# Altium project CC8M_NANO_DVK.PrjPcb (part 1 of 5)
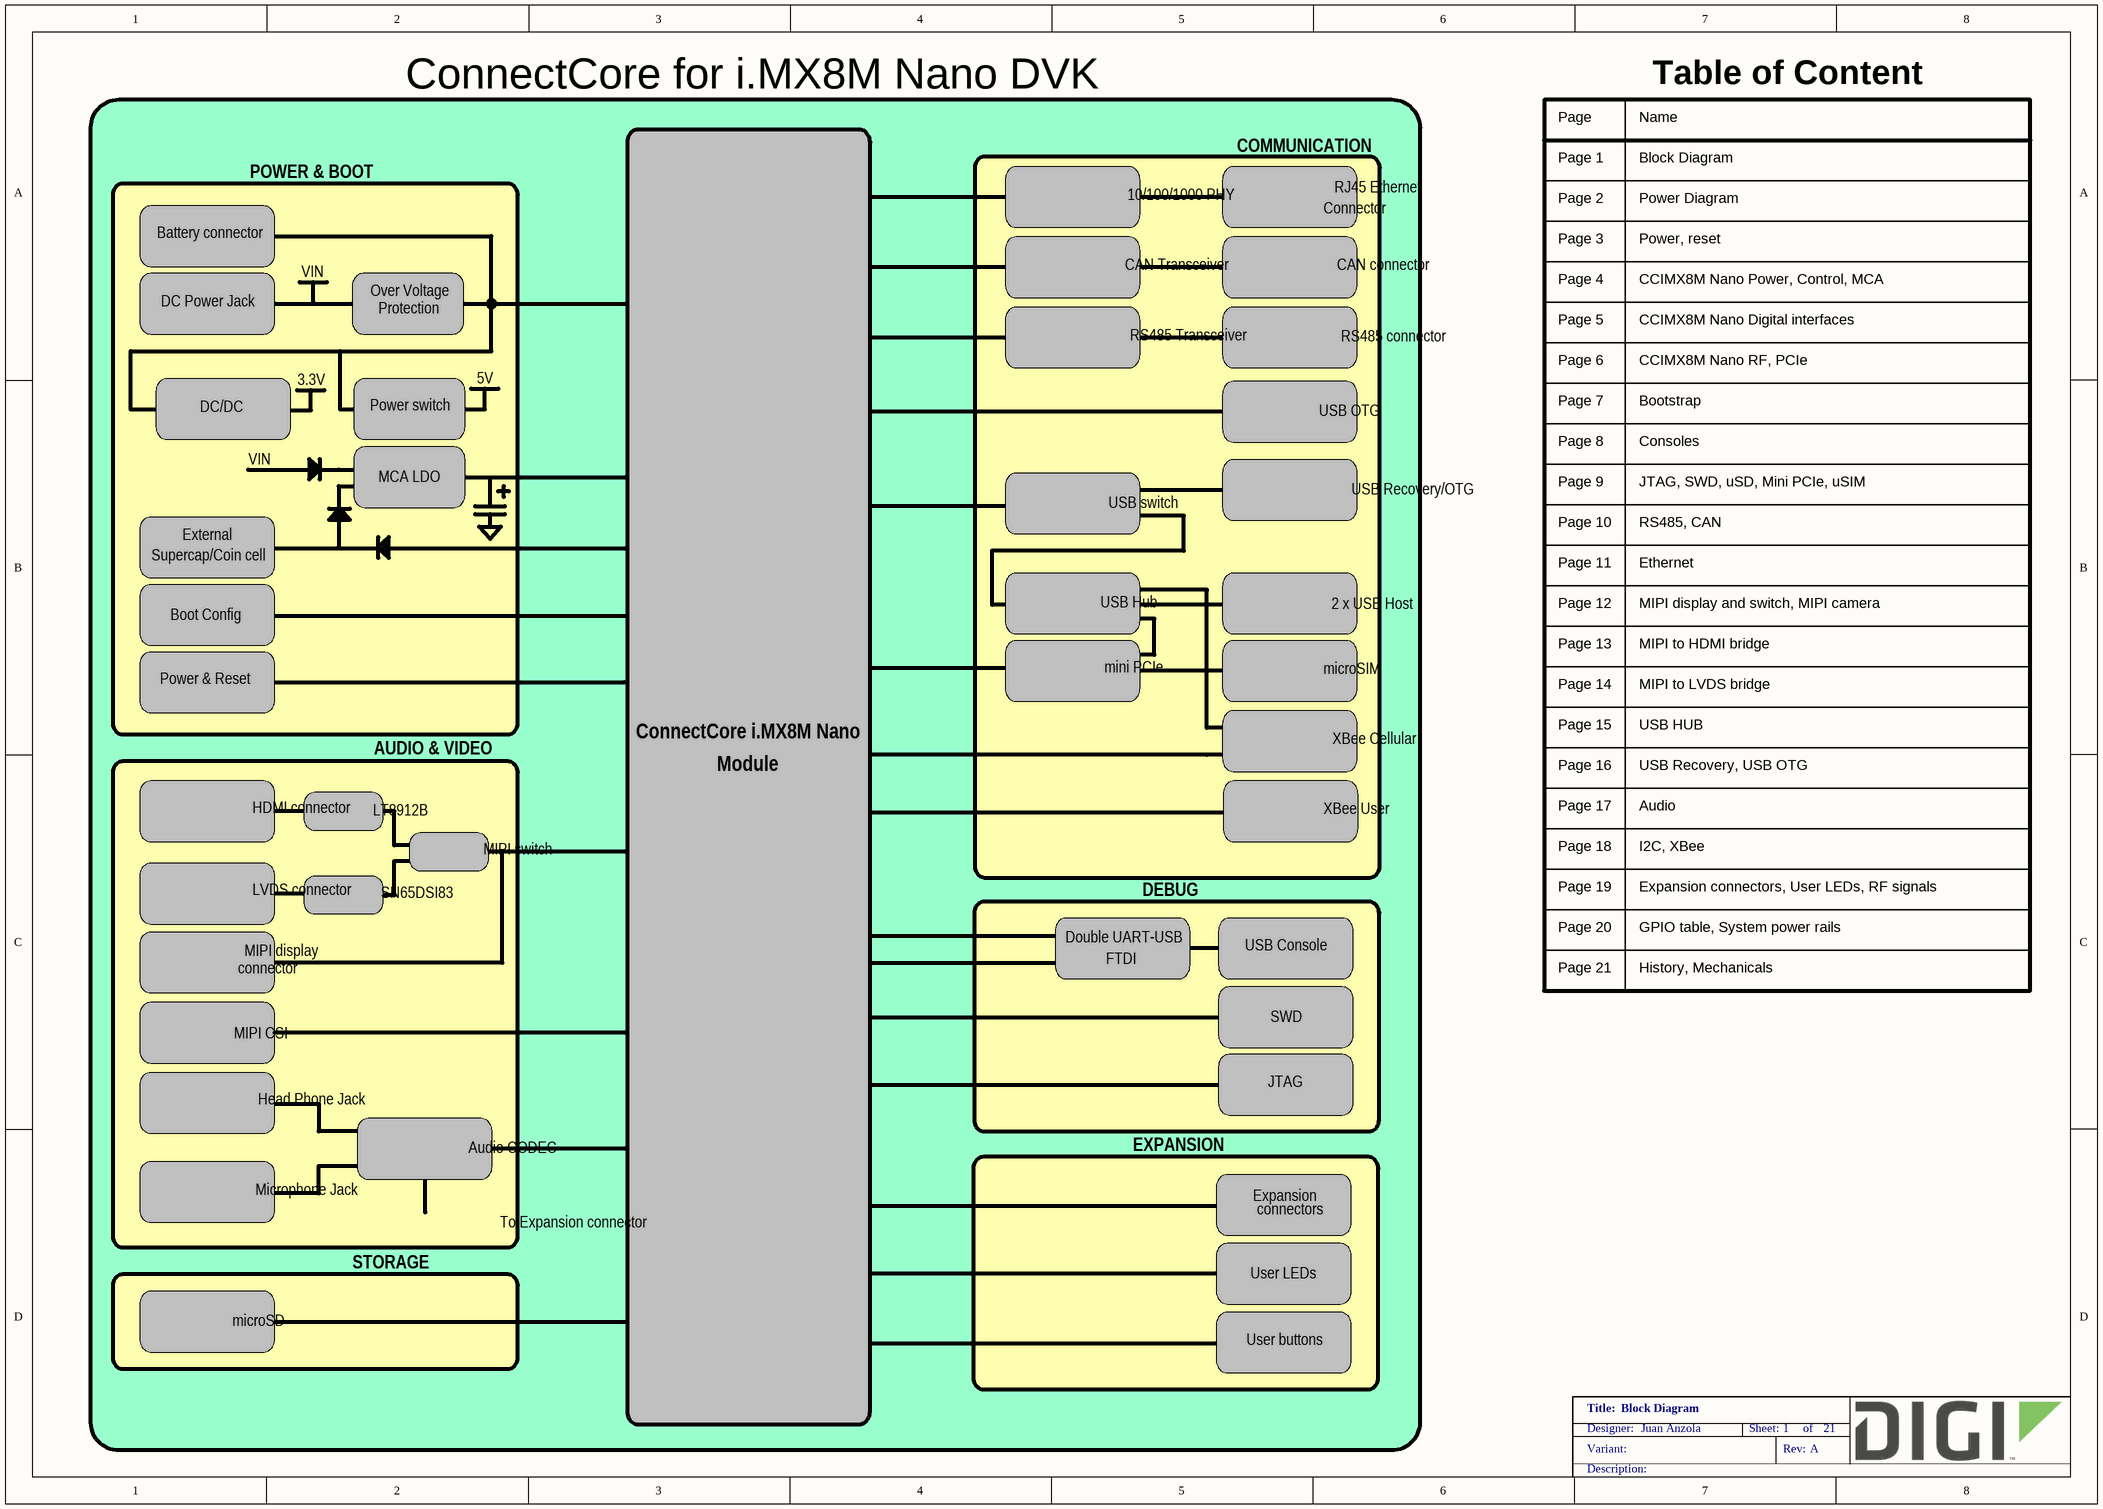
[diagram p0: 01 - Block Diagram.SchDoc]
VariantRevision: A
21 sheets, 756 parts. Net scope: flat (ports and power ports of the same name join across sheets).
Board file: 30016232-02_A.PcbDoc
Sheets:
  01 - Block Diagram.SchDoc
  02 - Power Diagram.SchDoc
  03 - Power, reset.SchDoc
  04 - CCIMX8M Nano Power, Control, MCA.SchDoc
  05 - CCIMX8M Nano Digital interfaces.SchDoc
  06 - CCIMX8M Nano RF, PCIe.SchDoc
  07 - Bootstrap.SchDoc
  08 - Consoles.SchDoc
  09 - JTAG, SWD, uSD, Mini PCIe, uSIM.SchDoc
  10 - RS485, CAN.SchDoc
  11 - Ethernet.SchDoc
  12 - MIPI display and switch, MIPI camera.SchDoc
  13 - MIPI to HDMI bridge.SchDoc
  14 - MIPI to LVDS bridge.SchDoc
  15 - USB HUB.SchDoc
  16 - USB Recovery, USB OTG.SchDoc
  17 - Audio.SchDoc
  18 - I2C, XBee.SchDoc
  19 - Expansion connectors, User LEDs, RF signals.SchDoc
  20 - GPIO Table, I2C Addresses.SchDoc
  21 - History, Mechanicals.SchDoc

## Sheet 01 - Block Diagram.SchDoc: Block Diagram
size A3; PageSetup: Record=PageOptions¦CenterHorizontal=True¦CenterVertical=True¦PrintScale=0.70¦XCorrection=1.00¦YCorrection=1.00¦PrintKind=0¦BorderSize=5000000¦LeftOffset=0¦BottomOffset=0¦Orientation=2¦PaperLength=4200¦PaperWidth=2970¦Scale=100¦PaperSource=7¦PrintQuality=600¦MediaType=1¦DitherType=10¦PaperKind=A4¦PrintScaleMode=1; Author: Juan Anzola; SheetNumber: 1; SheetTotal: 21

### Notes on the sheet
- ConnectCore for i.MX8M Nano DVK
- Table of Content
- POWER & BOOT
- COMMUNICATION
- Page 1
- Page
- Block Diagram
- Name
- Battery connector
- 10/100/1000 PHY
- Connector
- RJ45 Ethernet
- Page 2
- Page 3
- Power, reset
- Power Diagram
- DC Power Jack
- VIN
- Protection
- Over Voltage
- CAN Transceiver
- CAN connector
- Page 4
- CCIMX8M Nano Power, Control, MCA
- 5V
- RS485 Transceiver
- RS485 connector
- Page 5
- Page 6
- CCIMX8M Nano Digital interfaces
- CCIMX8M Nano RF, PCIe
- DC/DC
- 3.3V
- Power switch
- USB OTG
- Page 7
- Page 8
- Consoles
- Bootstrap
- MCA LDO
- USB switch
- USB Recovery/OTG
- Page 9
- JTAG, SWD, uSD, Mini PCIe, uSIM
- Supercap/Coin cell
- External
- Page 10
- Page 11
- RS485, CAN
- Ethernet
- Boot Config
- USB Hub
- 2 x USB Host
- Page 12
- Page 13
- MIPI display and switch, MIPI camera
- MIPI to HDMI bridge
- Power & Reset
- mini PCIe
- microSIM
- Page 14
- MIPI to LVDS bridge
- AUDIO & VIDEO
- ConnectCore i.MX8M Nano
- Module
- XBee Cellular
- Page 15
- Page 16
- USB HUB
- USB Recovery, USB OTG
- HDMI connector
- LT8912B
- MIPI switch
- XBee User
- Page 17
- Page 18
- Audio
- I2C, XBee
- LVDS connector
- SN65DSI83
- DEBUG
- Page 19
- Expansion connectors, User LEDs, RF signals
- connector
- MIPI display
- Double UART-USB
- FTDI
- USB Console
- Page 20
- Page 21
- History, Mechanicals
- GPIO table, System power rails
- MIPI CSI
- SWD
- Head Phone Jack
- JTAG
- Audio CODEC
- EXPANSION
- Microphone Jack
- To Expansion connector
- Expansion
- connectors
- microSD
- STORAGE
- User LEDs
- User buttons

## Sheet 02 - Power Diagram.SchDoc: Power Diagram
size A3; PageSetup: Record=PageOptions¦CenterHorizontal=True¦CenterVertical=True¦PrintScale=0.70¦XCorrection=1.00¦YCorrection=1.00¦PrintKind=0¦BorderSize=5000000¦LeftOffset=0¦BottomOffset=0¦Orientation=2¦PaperLength=4200¦PaperWidth=2970¦Scale=100¦PaperSource=7¦PrintQuality=600¦MediaType=1¦DitherType=10¦PaperKind=A4¦PrintScaleMode=1; Author: Juan Anzola; SheetNumber: 2; SheetTotal: 21
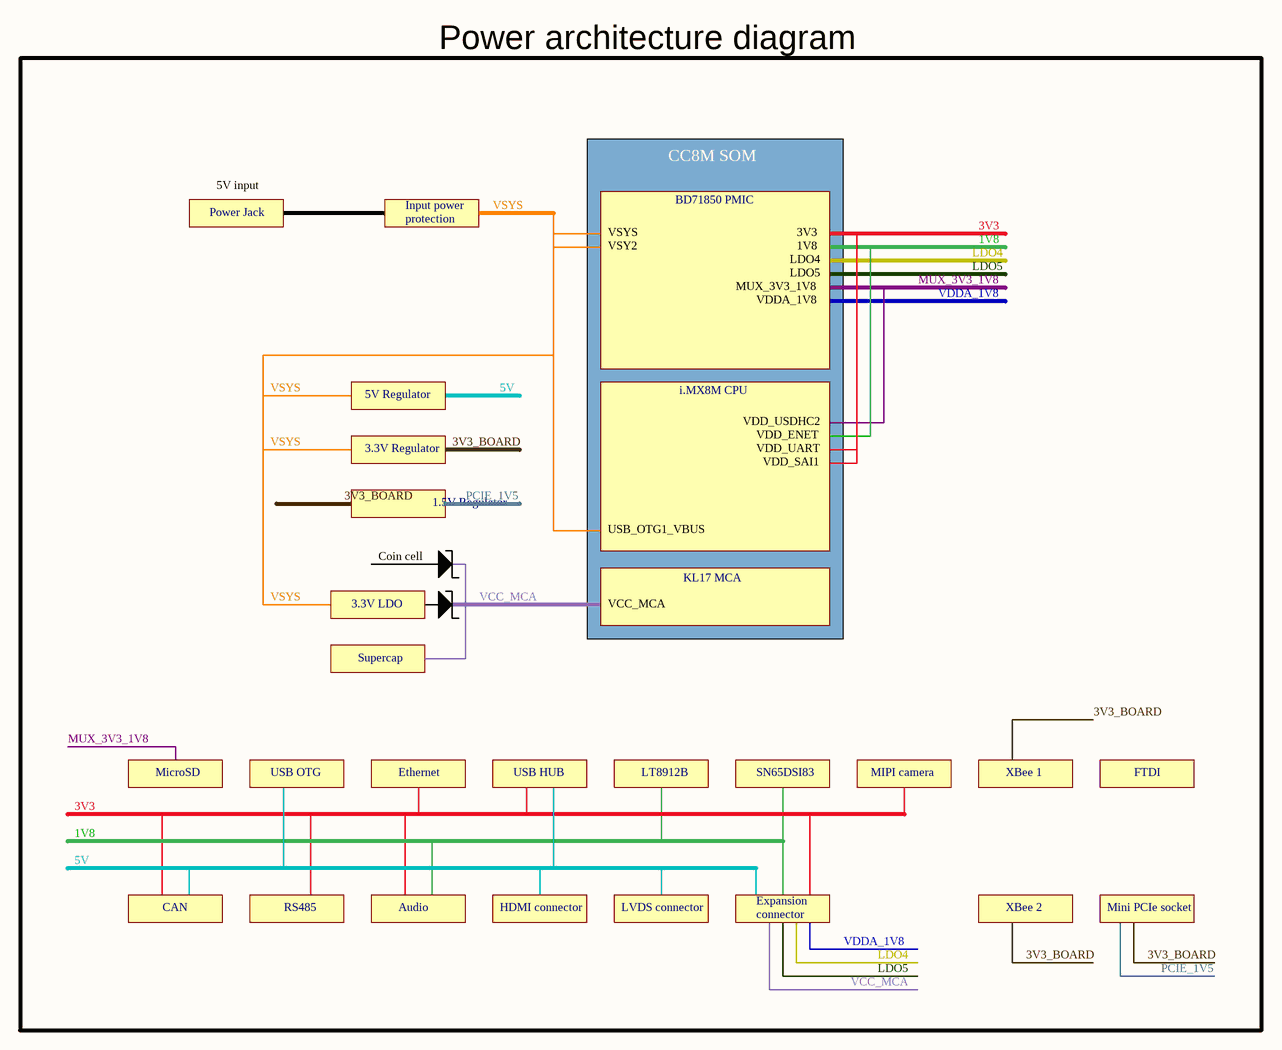
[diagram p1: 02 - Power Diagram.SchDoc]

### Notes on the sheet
- Power architecture diagram
- 5V input
- CC8M SOM
- BD71850 PMIC
- Power Jack
- Input power
- protection
- VSYS
- VSY2
- LDO4
- LDO5
- 3V3
- 1V8
- MUX_3V3_1V8
- VDDA_1V8
- 5V Regulator
- 5V
- i.MX8M CPU
- 3.3V Regulator
- 3V3_BOARD
- VDD_USDHC2
- VDD_ENET
- VDD_UART
- VDD_SAI1
- 1.5V Regulator
- PCIE_1V5
- USB_OTG1_VBUS
- 3.3V LDO
- Coin cell
- VCC_MCA
- KL17 MCA
- Supercap
- MicroSD
- USB OTG
- Ethernet
- USB HUB
- LT8912B
- SN65DSI83
- MIPI camera
- XBee 1
- FTDI
- CAN
- RS485
- Audio
- HDMI connector
- LVDS connector
- Expansion
- connector
- XBee 2
- Mini PCIe socket

## Sheet 03 - Power, reset.SchDoc: Power, reset
size A3; PageSetup: Record=PageOptions¦CenterHorizontal=True¦CenterVertical=True¦PrintScale=0.70¦XCorrection=1.00¦YCorrection=1.00¦PrintKind=0¦BorderSize=5000000¦LeftOffset=0¦BottomOffset=0¦Orientation=2¦PaperLength=4200¦PaperWidth=2970¦Scale=100¦PaperSource=7¦PrintQuality=600¦MediaType=1¦DitherType=10¦PaperKind=A4¦PrintScaleMode=1; Author: Juan Anzola; SheetNumber: 3; SheetTotal: 21
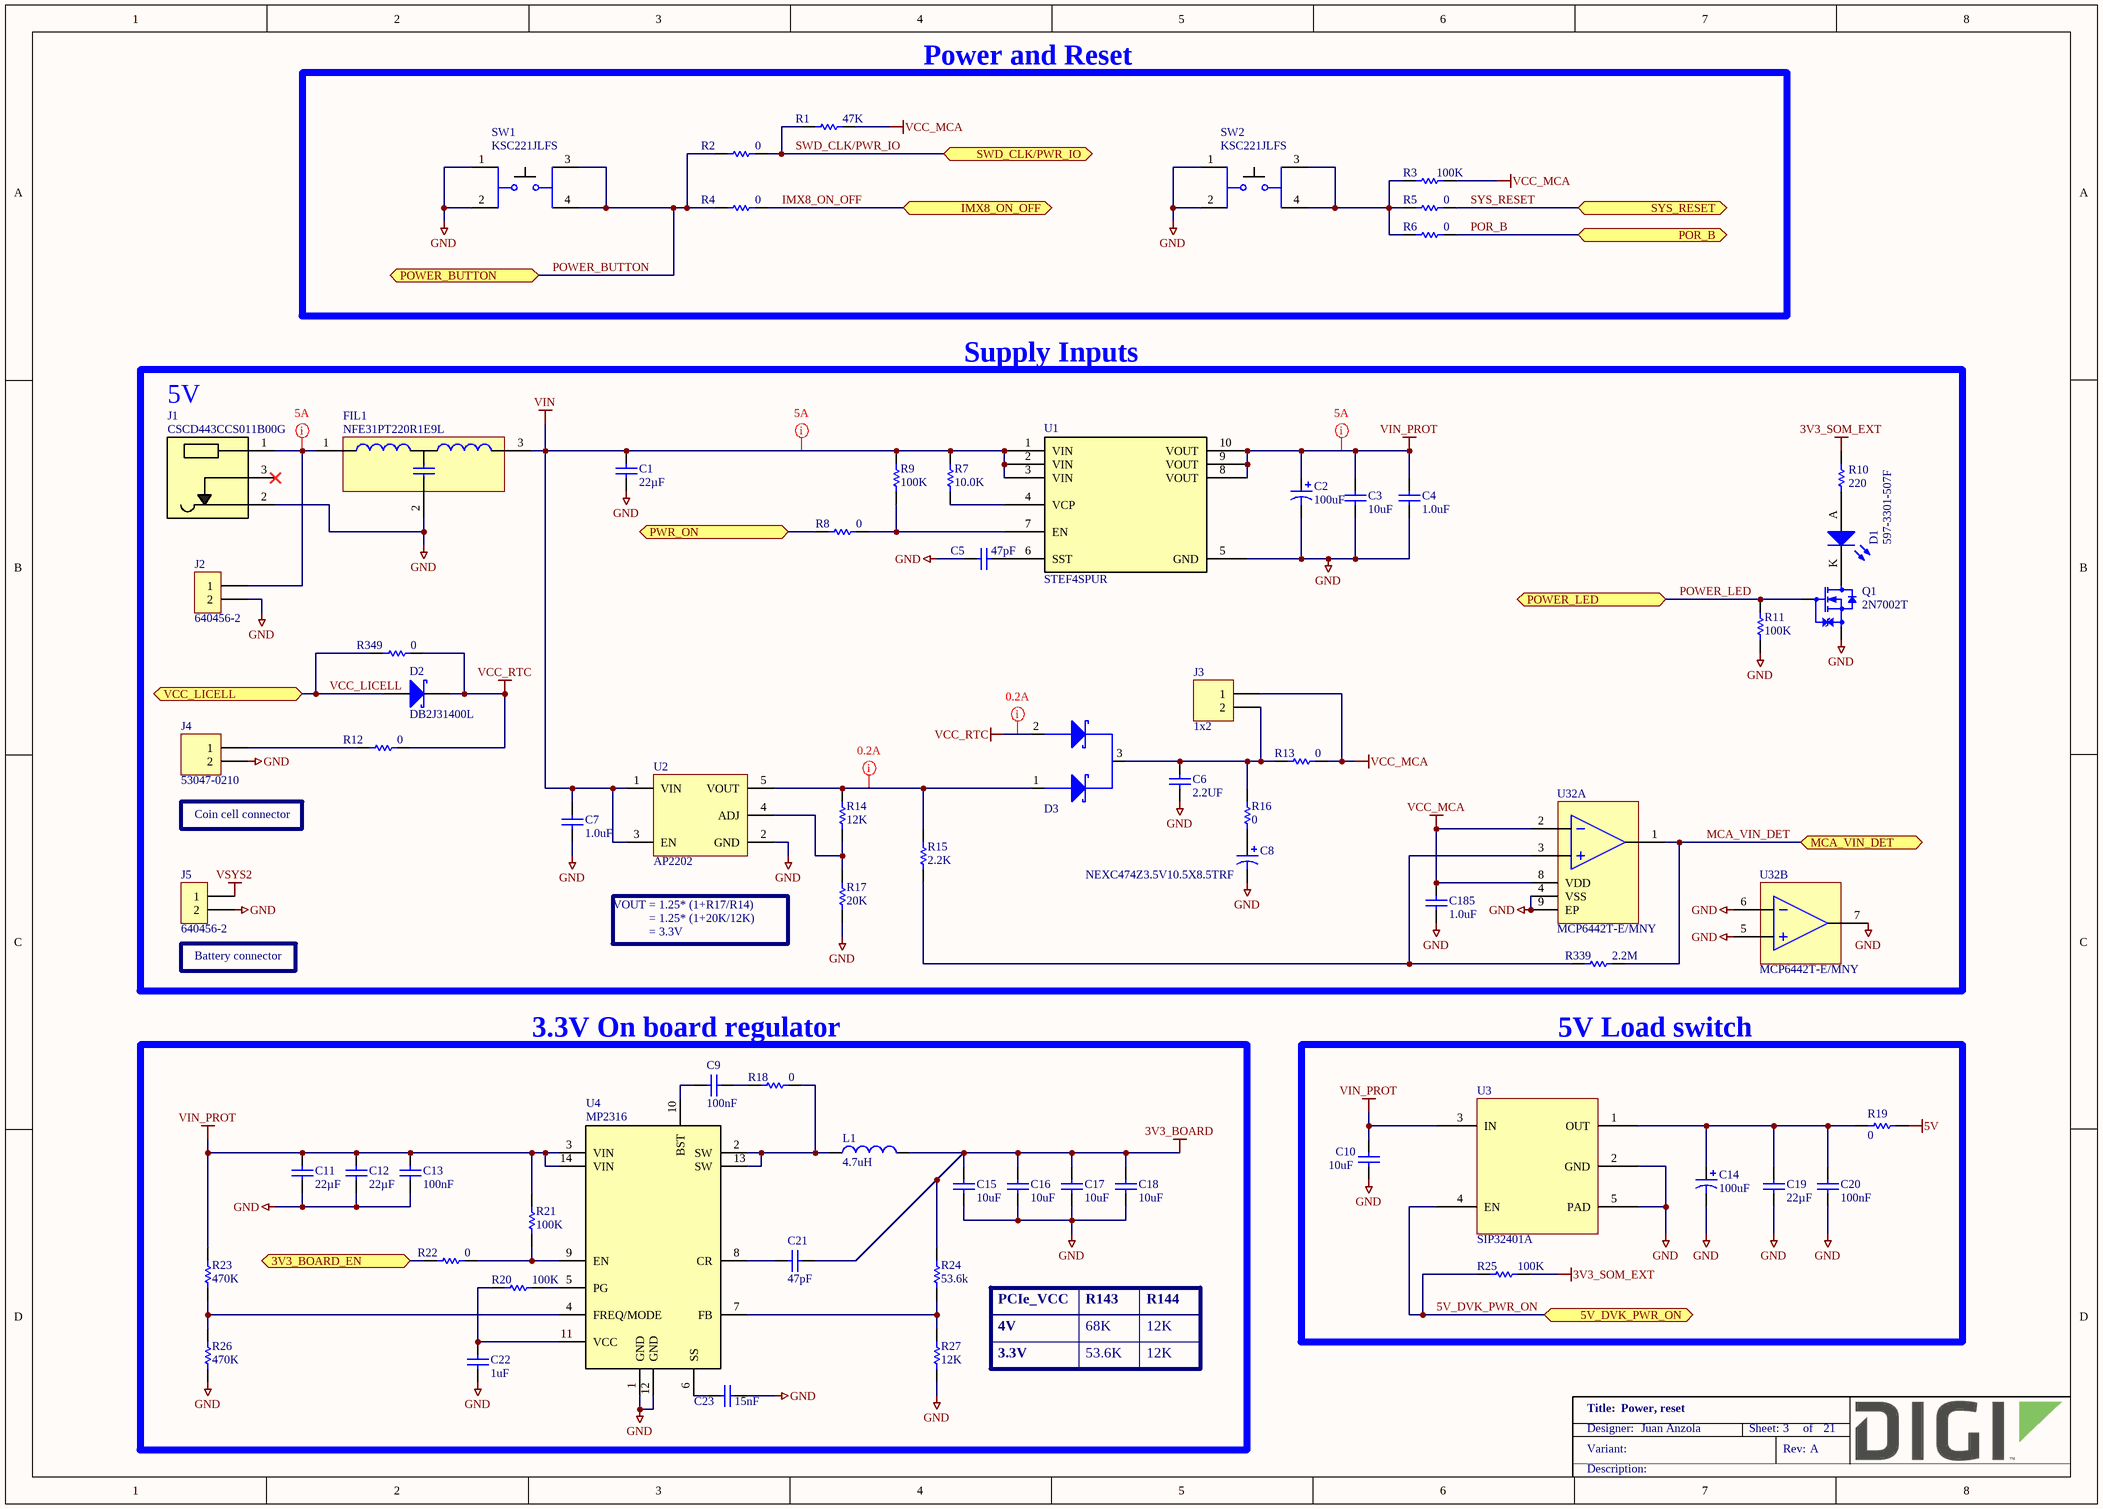
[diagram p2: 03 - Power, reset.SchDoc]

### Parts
C1  22µF  [CAPC1608X90N]
C2  100uF  [CAPMP3216X120N]
C3  10uF  [CAPC1005X55N]
C4  1.0uF  [CAPC1005X55N]
C5  47pF  [CAPC1005X55N]
C6  2.2UF  [CAPC1608X90N]
C7  1.0uF  [CAPC1005X55N]
C8  NEXC474Z3.5V10.5X8.5TRF  [NEXC474Z3.5V10.5X8.5TRF]
C9  100nF  [CAPC1005X55N]
C10  10uF  [CAPC1005X55N]
C11  22µF  [CAPC1608X90N]
C12  22µF  [CAPC1608X90N]
C13  100nF  [CAPC1005X55N]
C14  100uF  [CAPMP3216X120N]
C15  10uF  [CAPC2013X135N]
C16  10uF  [CAPC2013X135N]
C17  10uF  [CAPC2013X135N]
C18  10uF  [CAPC2013X135N]
C19  22µF  [CAPC1608X90N]
C20  100nF  [CAPC1005X55N]
C21  47pF  [CAPC1005X55N]
C22  1uF  [CAPC1608X90N]
C23  15nF  [CAPC1005X55N]
C185  1.0uF  [CAPC1005X55N]
D1  597-3301-507F  [LEDM3020X130N]
D2  DB2J31400L  [SODFL2513X80N]
D3  BAT54CWT1G  [SOT65P210X100-3AN]  (value not drawn)
FIL1  NFE31PT220R1E9L  [FIL_NFE31P]
J1  CSCD443CCS011B00G  [conn_CSCD443CCS011B00G]
J2  640456-2  [TE_640456-2]
J3  1x2  [FCI_68002-102HLF]
J4  Manufacturer_Part_Number: 53047-0210  [MOLEX_53047-0210_Flex]  (hidden comment: 1x2P)
J5  640456-2  [TE_640456-2]
L1  4.7uH  [IND_DG6045C]
Q1  2N7002T  [SOTFL50P160X80_GSD-3N]
R1  47K  [RESC1005X40N]
R2  0  [RESC1005X40N]
R3  100K  [RESC1005X40N]
R4  0  [RESC1005X40N]
R5  0  [RESC1005X40N]
R6  0  [RESC1005X40N]
R7  10.0K  [RESC1005X40N]
R8  0  [RESC1005X40N]
R9  100K  [RESC1005X40N]
R10  220  [RESC1005X40N]
R11  100K  [RESC1005X40N]
R12  0  [RESC1609X55N]
R13  0  [RESC1609X55N]
R14  12K  [RESC1609X55N]
R15  2.2K  [RESC1005X40N]
R16  0  [RESC1005X40N]
R17  20K  [RESC1609X55N]
R18  0  [RESC1609X55N]
R19  0  [RESC1609X55N]
R20  100K  [RESC1005X40N]
R21  100K  [RESC1005X40N]
R22  0  [RESC1005X40N]
R23  470K  [RESC1005X40N]
R24  53.6k  [RESC1609X55N]
R25  100K  [RESC1005X40N]
R26  470K  [RESC1005X40N]
R27  12K  [RESC1609X55N]
R339  2.2M  [RESC0603X28N]
R349  0  [RESC1609X55N]
SW1  KSC221JLFS  [SW_KSC221J]
SW2  KSC221JLFS  [SW_KSC221J]
U1  STEF4SPUR  [SON50P300X300X80-11T164X238N]
U2  AP2202  [SOT95P280X145-5N]
U3  SIP32401A  [SON50P120X160X60-5T55X91N]
U4  MP2316  [QFN_MPS_MP2316]
U32  MCP6442T-E/MNY  [SON50P300X200X80-9N]  (parts A,B of 2)

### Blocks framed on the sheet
Power and Reset: R1-R6 SW1 SW2
Supply Inputs: C1-C8 C185 D1-D3 FIL1 J1-J5 Q1 R7-R17 R339 R349 U1 U2 U32
3.3V On board regulator: C9 C11-C13 C15-C18 C21-C23 L1 R18 R20-R24 R26 R27 U4
5V Load switch: C10 C14 C19 C20 R19 R25 U3

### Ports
3V3_BOARD_EN (bidir), 5V_DVK_PWR_ON (bidir), IMX8_ON_OFF (bidir), MCA_VIN_DET (bidir), POR_B (bidir), POWER_BUTTON (bidir), POWER_LED (bidir), PWR_ON (bidir), SWD_CLK/PWR_IO (bidir), SYS_RESET (bidir), VCC_LICELL (bidir)

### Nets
3V3_BOARD: C15.2 C16.2 C17.2 C18.2 C21.2 L1.2 R24.2
3V3_SOM_EXT: R10.2 R25.2
5V: R19.2
GND: C1.1 C2.2 C3.1 C4.1 C5.1 C6.1 C7.1 C8.2 C10.1 C11.1 C12.1 C13.1 C14.2 C15.1 C16.1 C17.1 C18.1 C19.1 C20.1 C22.1 C23.1 C185.1 FIL1.2 J1.2 J2.2 J4.2 J5.2 Q1.S R11.2 R17.1 R26.1 R27.1 SW1.1 SW1.2 SW2.1 SW2.2 U1.5(GND) U2.2(GND) U3.2(GND) U3.5(PAD) U4.1(GND) U4.12(GND) U32.4(VSS) U32.5(VINB+) U32.6(VINB-) U32.7(VOUTB) U32.9(EP)
VCC_MCA: C185.2 J3.1 R1.2 R3.2 R13.2 U32.2(VIN-) U32.8(VDD)
VCC_RTC: D2.K D3.2 R12.2 R349.2
VIN: C1.2 C7.2 FIL1.3(GND) R7.2 R9.2 U1.1(VIN) U1.2(VIN) U1.3(VIN) U2.1(VIN) U2.3(EN)
VIN_PROT: C2.1 C3.2 C4.2 C10.2 C11.2 C12.2 C13.2 R21.2 R23.2 U1.8(VOUT) U1.9(VOUT) U1.10(VOUT) U3.3(IN) U4.3(VIN) U4.14(VIN)
VSYS2: J5.1
3V3_BOARD_EN: R22.1 ; port 3V3_BOARD_EN
5V_DVK_PWR_ON: R25.1 U3.4(EN) ; port 5V_DVK_PWR_ON
IMX8_ON_OFF: R4.2 ; port IMX8_ON_OFF
MCA_VIN_DET: R339.2 U32.1(VOUT) ; port MCA_VIN_DET
POR_B: R6.2 ; port POR_B
POWER_BUTTON: R2.1 R4.1 SW1.3 SW1.4 ; port POWER_BUTTON
POWER_LED: Q1.G R11.1 ; port POWER_LED
PWR_ON: R8.1 ; port PWR_ON
SWD_CLK/PWR_IO: R1.1 R2.2 ; port SWD_CLK/PWR_IO
SYS_RESET: R5.2 ; port SYS_RESET
VCC_LICELL: D2.A R349.1 ; port VCC_LICELL
NetC5_2: C5.2 U1.6(SST)
NetC6_2: C6.2 D3.3 J3.2 R13.1 R16.2
NetC8_1: C8.1 R16.1
NetC9_1: C9.1 U4.10(BST)
NetC9_2: C9.2 R18.1
NetC14_1: C14.1 C19.2 C20.2 R19.1 U3.1(OUT)
NetC21_1: C21.1 U4.8(CR)
NetC22_2: C22.2 R20.1 U4.11(VCC)
NetC23_2: C23.2 U4.6(SS)
NetD1_A: D1.A R10.1
NetD1_K: D1.K Q1.D
NetD3_1: D3.1 R14.2 R15.2 U2.5(VOUT)
NetFIL1_1: FIL1.1(GND) J1.1 J2.1
NetJ4_1: J4.1 R12.1
NetL1_1: L1.1 R18.2 U4.2(SW) U4.13(SW)
NetR3_1: R3.1 R5.1 R6.1 SW2.3 SW2.4
NetR7_1: R7.1 U1.4(VCP)
NetR8_2: R8.2 R9.1 U1.7(EN)
NetR14_1: R14.1 R17.2 U2.4(ADJ)
NetR15_1: R15.1 R339.1 U32.3(VIN+)
NetR20_2: R20.2 U4.5(PG)
NetR21_1: R21.1 R22.2 U4.9(EN)
NetR23_1: R23.1 R26.2 U4.4(FREQ/MODE)
NetR24_1: R24.1 R27.2 U4.7(FB)

Not connected (* = marked no-connect by the designer): J1 3*

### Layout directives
net class 0.2A: NetD3_1, VCC_RTC
net class 5A: NetFIL1_1, VIN, VIN_PROT

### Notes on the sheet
- 5V
- Coin cell connector
- (near J5) Battery connector
- VOUT = 1.25* (1+R17/R14)
  = 1.25* (1+20K/12K)
  = 3.3V
- PCIe_VCC
- R143
- R144
- 4V
- 3.3V
- 68K
- 53.6K
- 12K

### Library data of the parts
C1 = 1000998: CAP CER 22UF 10V 20% X5R 0603; Part_Type: Capacitor; Manufacturer: Samsung; Manufacturer_Part_Number: CL10A226MP8NUNE; Manufacturer_Alt_1: TDK Corporation; Manufacturer_Alt_1_Part_Number: C1608X5R1A226M080AC; Digi_PN: 14050684; Component_Life_Cycle_State: Reviewed; Area: 2,27; Tolerance: 20
C2 C14 = 1001196: CAP TANT 100UF 6.3V 20% 1206; Part_Type: Capacitor; Manufacturer: Rohm; Manufacturer_Part_Number: TCTAL0J107M8R; Digi_PN: 14050490; Component_Life_Cycle_State: Reviewed; Area: 8.01; Project: CCWMX6_SBC board
C3 C10 = 1001168: CAP CER 10UF 10V 20% X5R 0402; Part_Type: Capacitor; Manufacturer: Samsung; Manufacturer_Part_Number: CL05A106MP5NUNC; Digi_PN: 14050689; Component_Life_Cycle_State: Reviewed; Area: 0.95; Project: CCWMX6_SBC board
C4 = 1001167: CAP CER 1UF 10V 10% X5R 0402; Part_Type: Capacitor; Manufacturer: Murata; Manufacturer_Part_Number: GRM155R61A105KE15D; Digi_PN: 14050399; Component_Life_Cycle_State: Reviewed; Area: 0,95; Project: CCWMX6_SBC board
C5 = 1000007: CAP 47pF 50V 5% NP0 0402; Part_Type: Capacitor; Manufacturer: Murata; Manufacturer_Part_Number: GRM1555C1H470JA01D; Manufacturer_Alt_1: AVX Corporation; Manufacturer_Alt_1_Part_Number: 04025A470JAT2A; Note: 14050747 is Digi No. for GE WDNU; Digi_PN: 14050309; Component_Life_Cycle_State: CAD Reviewed; Area: 0,95; Temp_Coef: C0G, NP0
C6 = 1001303: CAP CER 2.2UF 16V 10% X5R 0603; Part_Type: Capacitor; Manufacturer: TDK Corporation; Manufacturer_Part_Number: C1608X5R1C225K080AB; Digi_PN: 14050730; Component_Life_Cycle_State: Reviewed; Area: 2,27; Project: Pinnacle
C7 = 1000073: CAP CER 1UF 6.3V 20% X5R 0402; Part_Type: Capacitor; Manufacturer: Murata; Manufacturer_Part_Number: GRM155R60J105ME19D; Digi_PN: 14050543; Component_Life_Cycle_State: Proven; Area: 0.95; Project: Adjustable Foundation
C8 = 1002775: SMCAP, 0.47F 3.5V SUPERCAP 8.5x10.5x10.8mm SMT; Part_Type: Capacitor; Manufacturer: NIC; Digi_PN: 14050629; Component_Life_Cycle_State: Pending
C9 C13 = 1000006: CAP 100nF 16V 10% X7R 0402; Part_Type: Capacitor; Manufacturer: Murata; Manufacturer_Part_Number: GRM155R71C104KA88D; Digi_PN: 14050552; Component_Life_Cycle_State: CAD Reviewed; Area: 0.95; Project: KITT; Tolerance: 10
C11 C12 C19 = 1000998: CAP CER 22UF 10V 20% X5R 0603; Part_Type: Capacitor; Manufacturer: Samsung; Manufacturer_Part_Number: CL10A226MP8NUNE; Manufacturer_Alt_1: TDK Corporation; Manufacturer_Alt_1_Part_Number: C1608X5R1A226M080AC; Digi_PN: 14050684; Component_Life_Cycle_State: Reviewed; Area: 2.27; Project: ConnectCore i.MX6 module; Tolerance: 20
C15-C18 = 1000111: CAP CER 10UF 16V 10% X5R 0805; Part_Type: Capacitor; Manufacturer: Murata; Manufacturer_Part_Number: GRM21BR61C106KE15L; Digi_PN: 14050701; Component_Life_Cycle_State: Proven; Area: 3.99; Project: Adjustable Foundation; Tolerance: 10
C20 = 1000006: CAP 100nF 16V 10% X7R 0402; Part_Type: Capacitor; Manufacturer: Murata; Manufacturer_Part_Number: GRM155R71C104KA88D; Component_Life_Cycle_State: CAD Reviewed; Area: 0.95; Project: KITT; Tolerance: 10; Digi_PN: 14050552
C21 = 1000007: CAP 47pF 50V 5% NP0 0402; Part_Type: Capacitor; Manufacturer: Murata; Manufacturer_Part_Number: GRM1555C1H470JA01D; Manufacturer_Alt_1: AVX Corporation; Manufacturer_Alt_1_Part_Number: 04025A470JAT2A; Note: 14050747 is Digi No. for GE WDNU; Digi_PN: 14050309; Component_Life_Cycle_State: CAD Reviewed; Area: 0.95; Project: KITT; Temp_Coef: C0G, NP0
C22 = 1000110: CAP CER 1UF 25V 10% X5R 0603; Part_Type: Capacitor; Manufacturer: Murata; Manufacturer_Part_Number: GRM188R61E105KA12D; Manufacturer_Alt_1: AVX Corporation; Manufacturer_Alt_1_Part_Number: TMK107BJ105KA-T; Note: 14050758  = Digi No. for GE WDNU; Digi_PN: 14050618; Component_Life_Cycle_State: Reviewed; Area: 2.27; Project: Adjustable Foundation
C23 = 1000512: CAP CER 0.015UF 16V 10% X7R 0402; Part_Type: Capacitor; Manufacturer: Murata; Manufacturer_Part_Number: GRM155R71C153KA01D; Digi_PN: 14050713; Component_Life_Cycle_State: CAD Reviewed; Area: 0.95; Project: Cellular Proof of Concept
C185 = 1000073: CAP CER 1UF 6.3V 20% X5R 0402; Part_Type: Capacitor; Manufacturer: Murata; Manufacturer_Part_Number: GRM155R60J105ME19D; Digi_PN: 14050543; Component_Life_Cycle_State: Proven; Area: 0,95
D1 = 1001189: LED GREEN 573NM 1208 SMD; Manufacturer: Dialight; Digi_PN: 17050183; Component_Life_Cycle_State: Reviewed; Area: 6; Project: CCWMX6_SBC board; Note: 17050846 = Digi PN for GE WDNU II
D2 = 1002592: DIODE SCHOTTKY 30V 30MA SMINI2; Part_Type: Diodes; Manufacturer: Panasonic - ECG; Digi_PN: 17000142; Component_Life_Cycle_State: Reviewed; Area: 6,06; Project: DIGI CC8X SOM
D3 = 1000794: DIODE SCHOTTKY 30V 200MA SOT323; Part Number: SDS1920004; Manufacturer: Fairchild Semiconductor; Manufacturer Alt 1: none; Manufacturer Part Num: 0082610201; Part_Type: Diodes; Digi_PN: 17050561; Component_Life_Cycle_State: CAD Reviewed; Area: 7,68; Project: SmartMeter2
FIL1 = 1002745: FILTER LC(T) 22PF SMD; Manufacturer: Murata; Digi_PN: 21000602; Component_Life_Cycle_State: Created; Area: 15
J1 = 1001105: DC Power Jack; Part_Type: Connector; Manufacturer: Bobbintron Electrical Corp; Digi_PN: 18000302; Component_Life_Cycle_State: Reviewed; Area: 137; Project: CCWMX6_SBC board
J2 J5 = 1002003: CONN HEADER VERT 2POS .100 TIN; Part_Type: Connector; Manufacturer: TE Connectivity; Digi_PN: 18050128; Component_Life_Cycle_State: Created; Area: 29,05; Project: iMX6UL+PMIC
J3 = 1001128: CONN HEADER 2POS .100" SGL GOLD; Part_Type: Connector; Manufacturer: Samtec; Manufacturer_Part_Number: TSW-102-07-G-S; Digi_PN: 00120002; Component_Life_Cycle_State: Reviewed; Area: 12,9032
J4 = 1001136: CONN HEADER 2POS 1.25MM VERT TIN; Part_Type: Connector; Manufacturer: Molex; Component_Life_Cycle_State: Reviewed; Area: 13.6; Project: CCWMX6_SBC board; Digi_PN: 18050343
L1 = 1002747: FIXED IND 4.7UH 4.5A 27.6 MOHM; Manufacturer: Murata; Manufacturer_Part_Number: 1255AY-4R7M=P3; Digi_PN: 21000603; Component_Life_Cycle_State: Reviewed; Area: 49
Q1 = 1000715: MOSFET N-CH 60V 115MA SOT-523F; Part_Type: Transistor; Manufacturer: Fairchild Semiconductor; Digi_PN: 17050797; Component_Life_Cycle_State: CAD Reviewed; Area: 3.06; Project: SmartMeter2; Note: 17050841 = Digi No. for GE WDNU
R1 = 1001155: RES 47.0K OHM 1/16W 1% 0402 SMD; Part_Type: Resistor; Manufacturer: Vishay Dale; Manufacturer_Part_Number: CRCW040247K0FKED; Digi_PN: 13050646; Component_Life_Cycle_State: Reviewed; Area: 0.95; Project: CCWMX6_SBC board
R2 R4-R6 R8 R22 = 1000076: RES 0.0 OHM 1/10W 0402 SMD; Part_Type: Resistor; Manufacturer: Panasonic - ECG; Manufacturer_Part_Number: ERJ-2GE0R00X; Component_Life_Cycle_State: Proven; Area: 0.95; Project: Adjustable Foundation; Power_WV_SRF: 10; Digi_PN: 13050387
R3 = 1000480: RES 100K OHM 1/10W 1% 0402 SMD; Part_Type: Resistor; Manufacturer: Panasonic - ECG; Manufacturer_Part_Number: ERJ-2RKF1003X; Digi_PN: 13051063; Component_Life_Cycle_State: CAD Reviewed; Area: 0,95; Project: KITT; Power_WV_SRF: 100
R7 = 1000537: RES 10.0K OHM 1/10W 1% 0402 SMD; Part_Type: Resistor; Manufacturer: Panasonic - ECG; Manufacturer_Part_Number: ERJ-2RKF1002X; Component_Life_Cycle_State: CAD Reviewed; Area: 0.95; Project: KITT; Power_WV_SRF: 100; Digi_PN: 13051084
R9 = 1000480: RES 100K OHM 1/10W 1% 0402 SMD; Part_Type: Resistor; Manufacturer: Panasonic - ECG; Manufacturer_Part_Number: ERJ-2RKF1003X; Digi_PN: 13051063; Component_Life_Cycle_State: CAD Reviewed; Area: 0,95; Power_WV_SRF: 100
R10 = 1001154: RES 220 OHM 1/16W 1% 0402 SMD; Part_Type: Resistor; Manufacturer: Yageo; Manufacturer_Part_Number: RC0402FR-07220RL; Digi_PN: 13050623; Component_Life_Cycle_State: Reviewed; Area: 0.95; Project: CCWMX6_SBC board
R11 R20 R21 R25 = 1000480: RES 100K OHM 1/10W 1% 0402 SMD; Part_Type: Resistor; Manufacturer: Panasonic - ECG; Manufacturer_Part_Number: ERJ-2RKF1003X; Digi_PN: 13051063; Component_Life_Cycle_State: CAD Reviewed; Area: 0.95; Project: KITT; Power_WV_SRF: 100
R12 R13 R18 R349 = 1000208: RES 0.0 OHM 1/10W 0603; Part_Type: Resistor; Manufacturer: Panasonic - ECG; Manufacturer_Part_Number: ERJ-3GEY0R00V; Note: 13051103 = Digi No. for GE WDNU; Digi_PN: 13050568; Component_Life_Cycle_State: Reviewed; Area: 2,5; Voltage: 75V
R14 = 1001200: RES 12.0K OHM 1/10W 1% 0603 SMD; Part_Type: Resistor; Manufacturer: Yageo; Manufacturer_Part_Number: RC0603FR-0712KL; Digi_PN: 13050531; Component_Life_Cycle_State: Reviewed; Area: 2,5; Project: LuCoV2; Power_WV_SRF: 100; Tolerance: 1
R15 = 1001156: RES 2.20K OHM 1/16W 1% 0402 SMD; Part_Type: Resistor; Manufacturer: Yageo; Manufacturer_Part_Number: RC0402FR-072K2L; Note: 13051099 = Digi No. for GE WDNU; Digi_PN: 13050699; Component_Life_Cycle_State: Reviewed; Area: 0,95
R16 = 1000076: RES 0.0 OHM 1/10W 0402 SMD; Part_Type: Resistor; Manufacturer: Panasonic - ECG; Manufacturer_Part_Number: ERJ-2GE0R00X; Digi_PN: 13050387; Component_Life_Cycle_State: Proven; Area: 0,95; Power_WV_SRF: 10
R17 = 1000142: RES 20K OHM 1/10W 5% 0603 SMD; Part_Type: Resistor; Manufacturer: Panasonic - ECG; Manufacturer_Part_Number: ERJ-3GEYJ203V; Digi_PN: 13050013; Component_Life_Cycle_State: Reviewed; Area: 2,5; Project: Adjustable Foundation; Power_WV_SRF: 100; Tolerance: 5
R19 = 1000208: RES 0.0 OHM 1/10W 0603; Part_Type: Resistor; Manufacturer: Panasonic - ECG; Manufacturer_Part_Number: ERJ-3GEY0R00V; Note: 13051103 = Digi No. for GE WDNU; Digi_PN: 13050568; Component_Life_Cycle_State: Reviewed; Area: 2.5; Project: Adjustable Foundation; Voltage: 75V
R23 R26 = 1000701: RES 470K OHM 1/10W 1% 0402 SMD; Part_Type: Resistor; Manufacturer: Panasonic - ECG; Manufacturer_Part_Number: ERJ-2RKF4703X; Digi_PN: 13051092; Component_Life_Cycle_State: CAD Reviewed; Area: 0.95; Project: KITT; Power_WV_SRF: 100
R24 = 1001518: RES 53.6K OHM 1/10W 1% 0603 SMD; Part_Type: Resistor; Manufacturer: Panasonic - ECG; Manufacturer_Part_Number: ERJ-3EKF5362V; Digi_PN: 13051064; Component_Life_Cycle_State: Reviewed; Area: 2.5; Project: WDNU-II
R27 = 1001200: RES 12.0K OHM 1/10W 1% 0603 SMD; Part_Type: Resistor; Manufacturer: Yageo; Manufacturer_Part_Number: RC0603FR-0712KL; Digi_PN: 13050531; Component_Life_Cycle_State: Reviewed; Area: 2.5; Project: LuCoV2; Power_WV_SRF: 100; Tolerance: 1
R339 = 1000980: RES 2.2M OHM 1/20W 5% 0201 SMD; Part_Type: Resistor; Manufacturer: Rohm; Manufacturer_Part_Number: MCR006YZPJ225; Manufacturer_Alt_1: Panasonic - ECG; Manufacturer_Alt_1_Part_Number: ERJ-1GEJ225C; Digi_PN: 13050884; Component_Life_Cycle_State: Reviewed; Area: 1,73; Power_WV_SRF: 50; Tolerance: 5
SW1 SW2 = 1001124: SWITCH TACTILE SPST-NO 0.05A 32V; Manufacturer: ITT; Digi_PN: 22000059; Component_Life_Cycle_State: Reviewed; Area: 37; Project: CCWMX6_SBC board; Note: 22000295 = Digi No. for GE WDNU
U1 = 1002744: IC ELECTRONIC FUSE 10VFDFPN; Manufacturer: STMicroelectronics; Digi_PN: 16000208; Component_Life_Cycle_State: Created; Area: 14,77
U2 = 1001979: IC REG LDO ADJ 0.15A SOT25; Part_Type: Regulator; Manufacturer: Diodes, Inc.; Manufacturer_Part_Number: AP2202K-ADJTRG1; Digi_PN: 17050874; Component_Life_Cycle_State: Created; Area: 8,9; Project: iMX6UL+PMIC
U3 = 1001857: IC SW W/CTRL SLEW RATE 4TDFN; Manufacturer: Vishay Siliconix; Manufacturer_Part_Number: SIP32401ADNP-T1GE4; Component_Life_Cycle_State: Reviewed; Area: 4.93; Project: CCWMX6_SBC board; Digi_PN: 16052004
U4 = 1001907: IC REG BUCK ADJ 3A SYNC; Manufacturer: Linear Technology; Manufacturer_Part_Number: MP2316GD; Digi_PN: 17050862; Component_Life_Cycle_State: Reviewed; Area: 9.375; Project: CCWMX6_SBC board
U32 = 1000217: IC OPAMP DUAL 1.6V 9KHZ 8TDFN; Manufacturer: Microchip; Digi_PN: 16000212; Component_Life_Cycle_State: Reviewed; Area: 7,4

## Sheet 04 - CCIMX8M Nano Power, Control, MCA.SchDoc: CCIMX8M Nano Power, Control, MCA
size A3; PageSetup: Record=PageOptions¦CenterHorizontal=True¦CenterVertical=True¦PrintScale=0.70¦XCorrection=1.00¦YCorrection=1.00¦PrintKind=0¦BorderSize=5000000¦LeftOffset=0¦BottomOffset=0¦Orientation=2¦PaperLength=4200¦PaperWidth=2970¦Scale=100¦PaperSource=7¦PrintQuality=600¦MediaType=1¦DitherType=10¦PaperKind=A4¦PrintScaleMode=1; Author: Juan Anzola; SheetNumber: 4; SheetTotal: 21
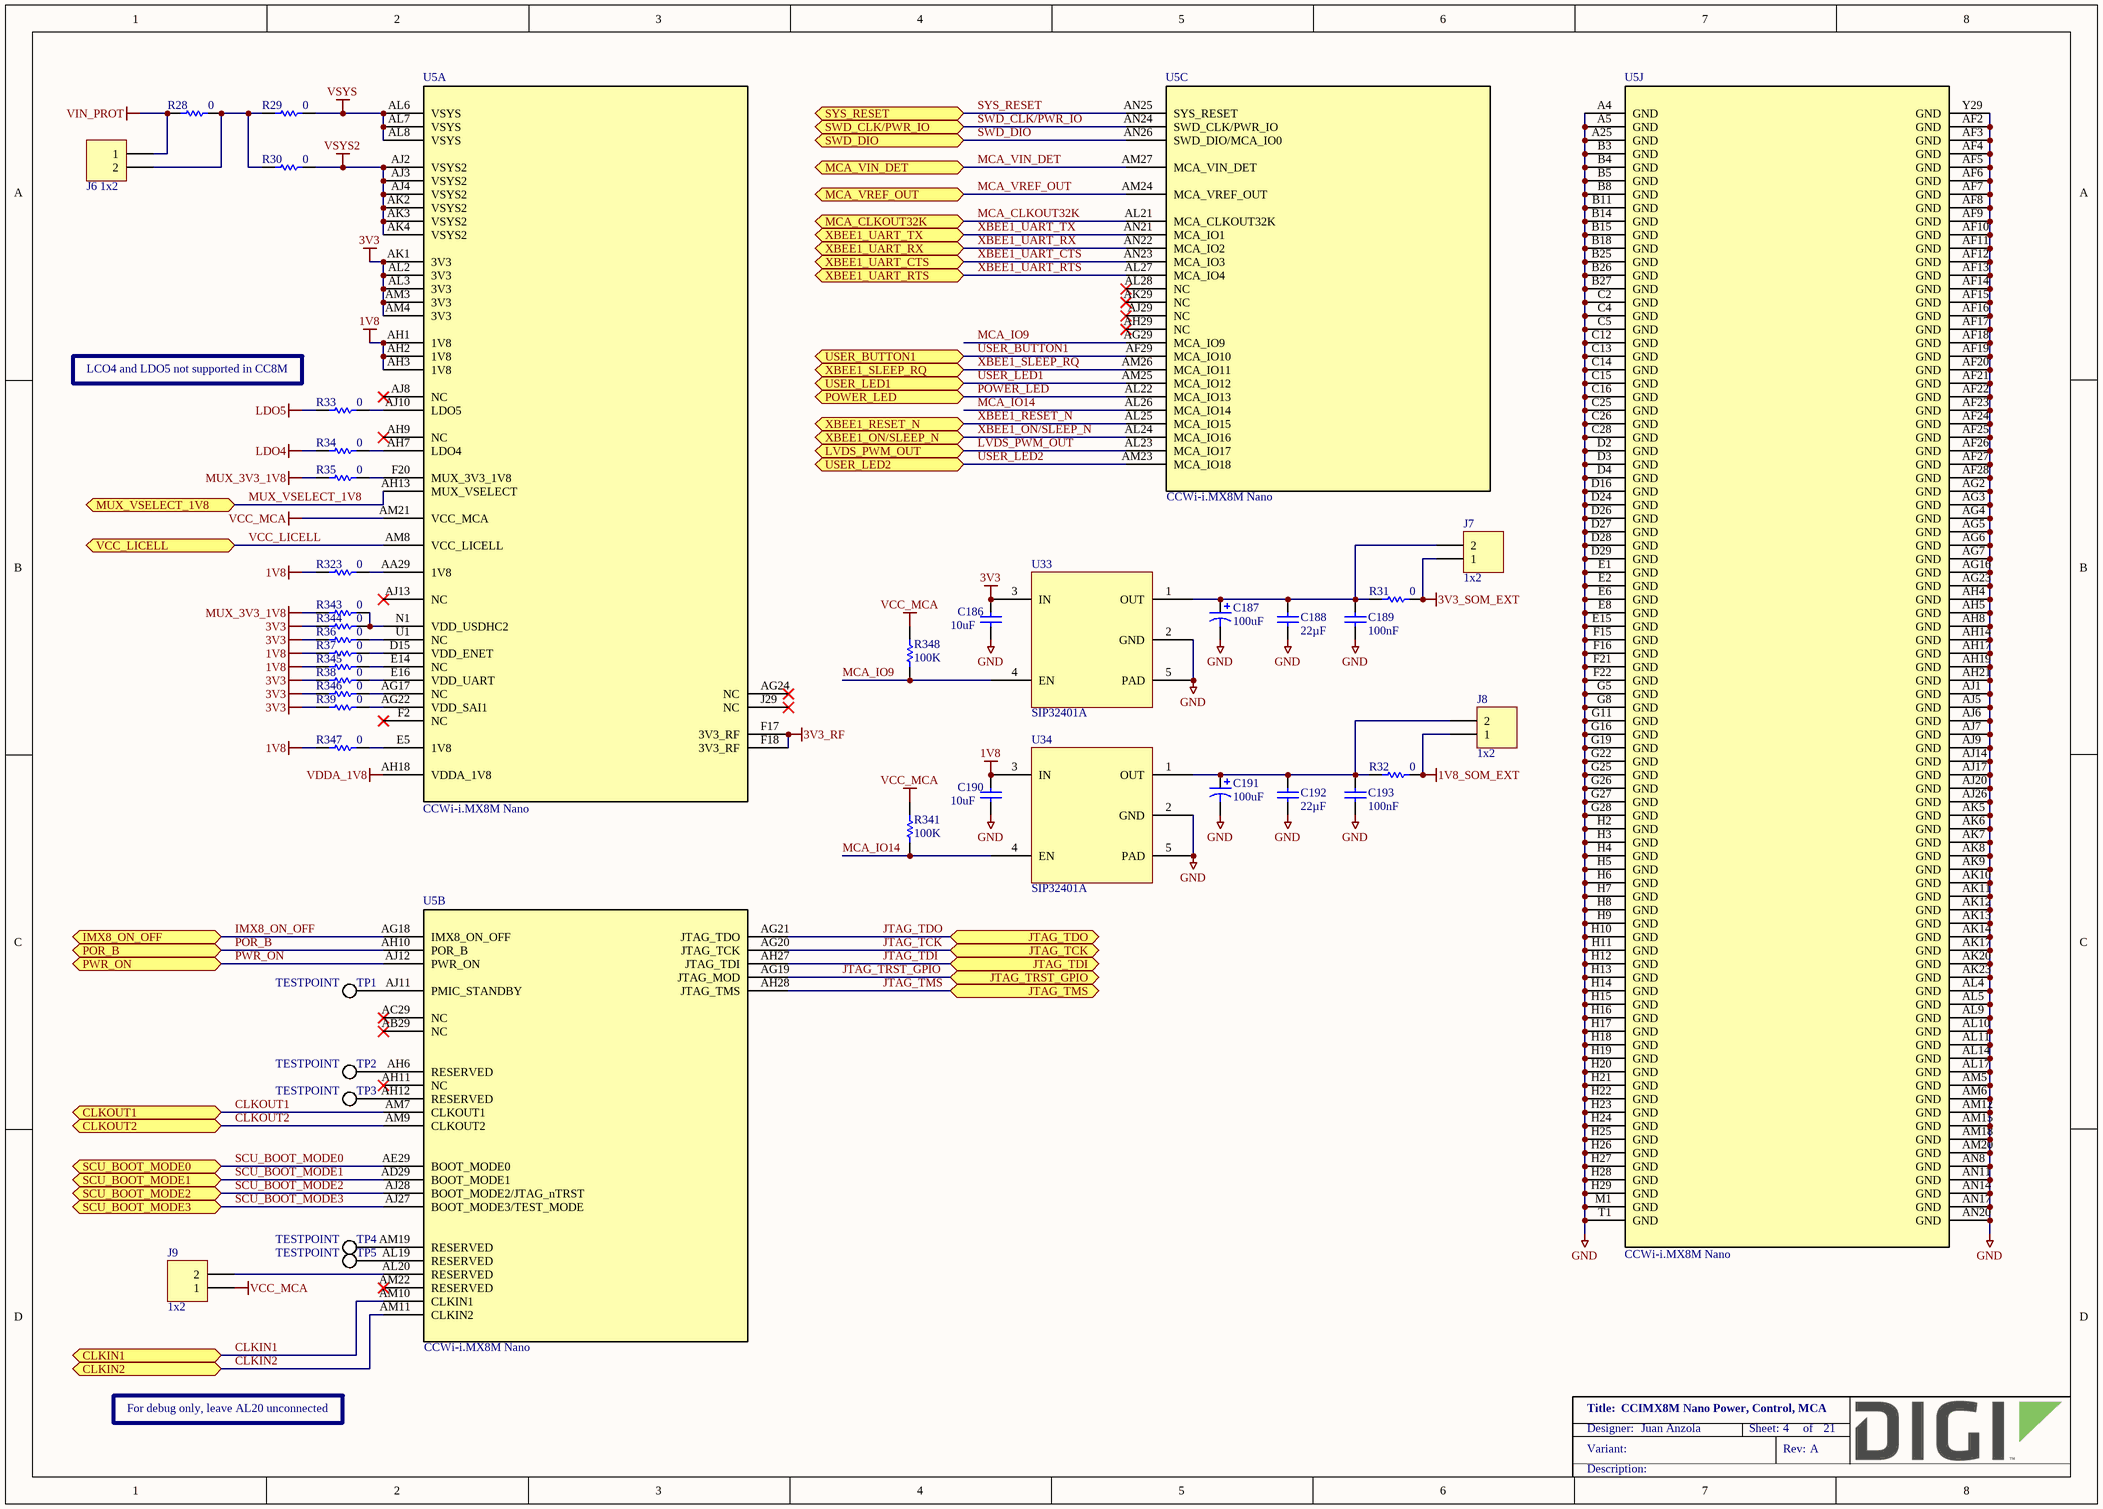
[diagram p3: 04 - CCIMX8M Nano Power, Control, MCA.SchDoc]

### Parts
C186  10uF  [CAPC1005X55N]
C187  100uF  [CAPMP3216X120N]
C188  22µF  [CAPC1608X90N]
C189  100nF  [CAPC1005X55N]
C190  10uF  [CAPC1005X55N]
C191  100uF  [CAPMP3216X120N]
C192  22µF  [CAPC1608X90N]
C193  100nF  [CAPC1005X55N]
J6  1x2  [FCI_68002-102HLF]
J7  1x2  [FCI_68002-102HLF]
J8  1x2  [FCI_68002-102HLF]
J9  1x2  [FCI_68002-102HLF]
R28  0  [RESC1609X55N]
R29  0  [RESC1609X55N]
R30  0  [RESC1609X55N]
R31  0  [RESC1609X55N]
R32  0  [RESC1609X55N]
R33  0  [RESC1609X55N]
R34  0  [RESC1609X55N]
R35  0  [RESC1609X55N]
R36  0  [RESC1005X40N]
R37  0  [RESC1005X40N]
R38  0  [RESC1005X40N]
R39  0  [RESC1005X40N]
R323  0  [RESC1005X40N]
R341  100K  [RESC1005X40N]
R343  0  [RESC1005X40N]
R344  0  [RESC1005X40N]
R345  0  [RESC1005X40N]
R346  0  [RESC1005X40N]
R347  0  [RESC1005X40N]
R348  100K  [RESC1005X40N]
TP1  TESTPOINT  [TP0762]  (no BOM)
TP2  TESTPOINT  [TP0762]  (no BOM)
TP3  TESTPOINT  [TP0762]  (no BOM)
TP4  TESTPOINT  [TP0762]  (no BOM)
TP5  TESTPOINT  [TP0762]  (no BOM)
U5  CCWi-i.MX8M Nano  [E-TEC_LPJ474-129M-32ABEW55L]  (parts A,B,C,J of 10)
U33  SIP32401A  [SON50P120X160X60-5T55X91N]
U34  SIP32401A  [SON50P120X160X60-5T55X91N]

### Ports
CLKIN1 (bidir), CLKIN2 (bidir), CLKOUT1 (bidir), CLKOUT2 (bidir), IMX8_ON_OFF (bidir), JTAG_TCK (bidir), JTAG_TDI (bidir), JTAG_TDO (bidir), JTAG_TMS (bidir), JTAG_TRST_GPIO (bidir), LVDS_PWM_OUT (bidir), MCA_CLKOUT32K (bidir), MCA_VIN_DET (bidir), MCA_VREF_OUT (bidir), MUX_VSELECT_1V8 (bidir), POR_B (bidir), POWER_LED (bidir), PWR_ON (bidir), SCU_BOOT_MODE0 (bidir), SCU_BOOT_MODE1 (bidir), SCU_BOOT_MODE2 (bidir), SCU_BOOT_MODE3 (bidir), SWD_CLK/PWR_IO (bidir), SWD_DIO (bidir), SYS_RESET (bidir), USER_BUTTON1 (bidir), USER_LED1 (bidir), USER_LED2 (bidir), VCC_LICELL (bidir), XBEE1_ON/SLEEP_N (bidir), XBEE1_RESET_N (bidir), XBEE1_SLEEP_RQ (bidir), XBEE1_UART_CTS (bidir), XBEE1_UART_RTS (bidir), XBEE1_UART_RX (bidir), XBEE1_UART_TX (bidir)

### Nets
1V8: C190.2 R37.1 R323.1 R345.1 R347.1 U5.AH1(1V8) U5.AH2(1V8) U5.AH3(1V8) U34.3(IN)
1V8_SOM_EXT: J8.1 R32.2
3V3: C186.2 R36.1 R38.1 R39.1 R344.1 R346.1 U5.AK1(3V3) U5.AL2(3V3) U5.AL3(3V3) U5.AM3(3V3) U5.AM4(3V3) U33.3(IN)
3V3_RF: U5.F17(3V3_RF) U5.F18(3V3_RF)
3V3_SOM_EXT: J7.1 R31.2
GND: C186.1 C187.2 C188.1 C189.1 C190.1 C191.2 C192.1 C193.1 U5.A25(GND) U5.A4(GND) U5.A5(GND) U5.AF2(GND) U5.AF3(GND) U5.AF4(GND) U5.AF5(GND) U5.AF6(GND) U5.AF7(GND) U5.AF8(GND) U5.AF9(GND) U5.AF10(GND) U5.AF11(GND) U5.AF12(GND) U5.AF13(GND) U5.AF14(GND) U5.AF15(GND) U5.AF16(GND) U5.AF17(GND) U5.AF18(GND) U5.AF19(GND) U5.AF20(GND) U5.AF21(GND) U5.AF22(GND) U5.AF23(GND) U5.AF24(GND) U5.AF25(GND) U5.AF26(GND) U5.AF27(GND) U5.AF28(GND) U5.AG2(GND) U5.AG3(GND) U5.AG4(GND) U5.AG5(GND) U5.AG6(GND) U5.AG7(GND) U5.AG16(GND) U5.AG23(GND) U5.AH4(GND) U5.AH5(GND) U5.AH8(GND) U5.AH14(GND) U5.AH17(GND) U5.AH19(GND) U5.AH21(GND) U5.AJ1(GND) U5.AJ5(GND) U5.AJ6(GND) U5.AJ7(GND) U5.AJ9(GND) U5.AJ14(GND) U5.AJ17(GND) U5.AJ20(GND) U5.AJ26(GND) U5.AK5(GND) U5.AK6(GND) U5.AK7(GND) U5.AK8(GND) U5.AK9(GND) U5.AK10(GND) U5.AK11(GND) U5.AK12(GND) U5.AK13(GND) U5.AK14(GND) U5.AK17(GND) U5.AK20(GND) U5.AK23(GND) U5.AL4(GND) U5.AL5(GND) U5.AL9(GND) U5.AL10(GND) U5.AL11(GND) U5.AL14(GND) U5.AL17(GND) U5.AM5(GND) U5.AM6(GND) U5.AM12(GND) U5.AM15(GND) U5.AM18(GND) U5.AM20(GND) U5.AN8(GND) U5.AN11(GND) U5.AN14(GND) U5.AN17(GND) U5.AN20(GND) U5.B3(GND) U5.B4(GND) U5.B5(GND) U5.B8(GND) U5.B11(GND) U5.B14(GND) U5.B15(GND) U5.B18(GND) U5.B25(GND) U5.B26(GND) U5.B27(GND) U5.C2(GND) U5.C4(GND) U5.C5(GND) U5.C12(GND) U5.C13(GND) U5.C14(GND) U5.C15(GND) U5.C16(GND) U5.C25(GND) U5.C26(GND) U5.C28(GND) U5.D2(GND) U5.D3(GND) U5.D4(GND) U5.D16(GND) U5.D24(GND) U5.D26(GND) U5.D27(GND) U5.D28(GND) U5.D29(GND) U5.E1(GND) U5.E2(GND) U5.E6(GND) U5.E8(GND) U5.E15(GND) U5.F15(GND) U5.F16(GND) U5.F21(GND) U5.F22(GND) U5.G5(GND) U5.G8(GND) U5.G11(GND) U5.G16(GND) U5.G19(GND) U5.G22(GND) U5.G25(GND) U5.G26(GND) U5.G27(GND) U5.G28(GND) U5.H2(GND) U5.H3(GND) U5.H4(GND) U5.H5(GND) U5.H6(GND) U5.H7(GND) U5.H8(GND) U5.H9(GND) U5.H10(GND) U5.H11(GND) U5.H12(GND) U5.H13(GND) U5.H14(GND) U5.H15(GND) U5.H16(GND) U5.H17(GND) U5.H18(GND) U5.H19(GND) U5.H20(GND) U5.H21(GND) U5.H22(GND) U5.H23(GND) U5.H24(GND) U5.H25(GND) U5.H26(GND) U5.H27(GND) U5.H28(GND) U5.H29(GND) U5.M1(GND) U5.T1(GND) U5.Y29(GND) U33.2(GND) U33.5(PAD) U34.2(GND) U34.5(PAD)
LDO4: R34.1
LDO5: R33.1
MUX_3V3_1V8: R35.1 R343.1
VCC_MCA: J9.1 R341.2 R348.2 U5.AM21(VCC_MCA)
VDDA_1V8: U5.AH18(VDDA_1V8)
VIN_PROT: J6.1 R28.1
VSYS: R29.2 U5.AL6(VSYS) U5.AL7(VSYS) U5.AL8(VSYS)
VSYS2: R30.2 U5.AJ2(VSYS2) U5.AJ3(VSYS2) U5.AJ4(VSYS2) U5.AK2(VSYS2) U5.AK3(VSYS2) U5.AK4(VSYS2)
CLKIN1: U5.AM10(CLKIN1) ; port CLKIN1
CLKIN2: U5.AM11(CLKIN2) ; port CLKIN2
CLKOUT1: U5.AM7(CLKOUT1) ; port CLKOUT1
CLKOUT2: U5.AM9(CLKOUT2) ; port CLKOUT2
IMX8_ON_OFF: U5.AG18(IMX8_ON_OFF) ; port IMX8_ON_OFF
JTAG_TCK: U5.AG20(JTAG_TCK) ; port JTAG_TCK
JTAG_TDI: U5.AH27(JTAG_TDI) ; port JTAG_TDI
JTAG_TDO: U5.AG21(JTAG_TDO) ; port JTAG_TDO
JTAG_TMS: U5.AH28(JTAG_TMS) ; port JTAG_TMS
JTAG_TRST_GPIO: U5.AG19(JTAG_MOD) ; port JTAG_TRST_GPIO
LVDS_PWM_OUT: U5.AL23(MCA_IO17) ; port LVDS_PWM_OUT
MCA_CLKOUT32K: U5.AL21(MCA_CLKOUT32K) ; port MCA_CLKOUT32K
MCA_IO9: R348.1 U5.AG29(MCA_IO9) U33.4(EN)
MCA_IO14: R341.1 U5.AL26(MCA_IO14) U34.4(EN)
MCA_VIN_DET: U5.AM27(MCA_VIN_DET) ; port MCA_VIN_DET
MCA_VREF_OUT: U5.AM24(MCA_VREF_OUT) ; port MCA_VREF_OUT
MUX_VSELECT_1V8: U5.AH13(MUX_VSELECT) ; port MUX_VSELECT_1V8
POR_B: U5.AH10(POR_B) ; port POR_B
POWER_LED: U5.AL22(MCA_IO13) ; port POWER_LED
PWR_ON: U5.AJ12(PWR_ON) ; port PWR_ON
SCU_BOOT_MODE0: U5.AE29(BOOT_MODE0) ; port SCU_BOOT_MODE0
SCU_BOOT_MODE1: U5.AD29(BOOT_MODE1) ; port SCU_BOOT_MODE1
SCU_BOOT_MODE2: U5.AJ28(BOOT_MODE2/JTAG_nTRST) ; port SCU_BOOT_MODE2
SCU_BOOT_MODE3: U5.AJ27(BOOT_MODE3/TEST_MODE) ; port SCU_BOOT_MODE3
SWD_CLK/PWR_IO: U5.AN24(SWD_CLK/PWR_IO) ; port SWD_CLK/PWR_IO
SWD_DIO: U5.AN26(SWD_DIO/MCA_IO0) ; port SWD_DIO
SYS_RESET: U5.AN25(SYS_RESET) ; port SYS_RESET
USER_BUTTON1: U5.AF29(MCA_IO10) ; port USER_BUTTON1
USER_LED1: U5.AM25(MCA_IO12) ; port USER_LED1
USER_LED2: U5.AM23(MCA_IO18) ; port USER_LED2
VCC_LICELL: U5.AM8(VCC_LICELL) ; port VCC_LICELL
XBEE1_ON/SLEEP_N: U5.AL24(MCA_IO16) ; port XBEE1_ON/SLEEP_N
XBEE1_RESET_N: U5.AL25(MCA_IO15) ; port XBEE1_RESET_N
XBEE1_SLEEP_RQ: U5.AM26(MCA_IO11) ; port XBEE1_SLEEP_RQ
XBEE1_UART_CTS: U5.AN23(MCA_IO3) ; port XBEE1_UART_CTS
XBEE1_UART_RTS: U5.AL27(MCA_IO4) ; port XBEE1_UART_RTS
XBEE1_UART_RX: U5.AN22(MCA_IO2) ; port XBEE1_UART_RX
XBEE1_UART_TX: U5.AN21(MCA_IO1) ; port XBEE1_UART_TX
NetC187_1: C187.1 C188.2 C189.2 J7.2 R31.1 U33.1(OUT)
NetC191_1: C191.1 C192.2 C193.2 J8.2 R32.1 U34.1(OUT)
NetJ6_2: J6.2 R28.2 R29.1 R30.1
NetJ9_2: J9.2 U5.AL20(RESERVED)
NetR33_2: R33.2 U5.AJ10(LDO5)
NetR34_2: R34.2 U5.AH7(LDO4)
NetR35_2: R35.2 U5.F20(MUX_3V3_1V8)
NetR36_2: R36.2 U5.U1(NC)
NetR37_2: R37.2 U5.D15(VDD_ENET)
NetR38_2: R38.2 U5.E16(VDD_UART)
NetR39_2: R39.2 U5.AG22(VDD_SAI1)
NetR323_2: R323.2 U5.AA29(1V8)
NetR343_2: R343.2 R344.2 U5.N1(VDD_USDHC2)
NetR345_2: R345.2 U5.E14(NC)
NetR346_2: R346.2 U5.AG17(NC)
NetR347_2: R347.2 U5.E5(1V8)
NetTP1_1: TP1.1 U5.AJ11(PMIC_STANDBY)
NetTP2_1: TP2.1 U5.AH6(RESERVED)
NetTP3_1: TP3.1 U5.AH12(RESERVED)
NetTP4_1: TP4.1 U5.AM19(RESERVED)
NetTP5_1: TP5.1 U5.AL19(RESERVED)

Not connected (* = marked no-connect by the designer): U5 AB29(NC)* AC29(NC)* AG24(NC)* AH9(NC)* AH11(NC)* AH29(NC)* AJ8(NC)* AJ13(NC)* AJ29(NC)* AK29(NC)* AL28(NC)* AM22(RESERVED)* F2(NC)* J29(NC)*

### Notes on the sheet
- (near R33) LCO4 and LDO5 not supported in CC8M
- For debug only, leave AL20 unconnected

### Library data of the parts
C186 C190 = 1001168: as C3 on sheet 03 - Power, reset
C187 C191 = 1001196: as C2 on sheet 03 - Power, reset
C188 C192 = 1000998: as C11 on sheet 03 - Power, reset
C189 C193 = 1000006: as C20 on sheet 03 - Power, reset
J6-J9 = 1001128: as J3 on sheet 03 - Power, reset
R28 = 1000208: as R12 on sheet 03 - Power, reset
R29-R35 = 1000208: RES 0.0 OHM 1/10W 0603; Part_Type: Resistor; Manufacturer: Panasonic - ECG; Manufacturer_Part_Number: ERJ-3GEY0R00V; Note: 13051103 = Digi No. for GE WDNU; Digi_PN: 13050568; Component_Life_Cycle_State: Reviewed; Area: 2,5; Project: Adjustable Foundation; Voltage: 75V
R36-R39 R323 = 1000076: RES 0.0 OHM 1/10W 0402 SMD; Part_Type: Resistor; Manufacturer: Panasonic - ECG; Manufacturer_Part_Number: ERJ-2GE0R00X; Digi_PN: 13050387; Component_Life_Cycle_State: Proven; Area: 0,95; Project: Adjustable Foundation; Power_WV_SRF: 10
R341 R348 = 1000480: as R11 on sheet 03 - Power, reset
R343-R347 = 1000076: as R16 on sheet 03 - Power, reset
TP1-TP5 = CAD0011: TEST POINT 30MIL PAD SMT; Component_Life_Cycle_State: Reviewed; Area: 0,58; Project: CLC
U5 = 1002739: ConnectCore for i.MX8M Nano module - LGA; Manufacturer: DIGI; Digi_PN: 50002014-01; Component_Life_Cycle_State: Pending
U33 U34 = 1001857: as U3 on sheet 03 - Power, reset

## Sheet 05 - CCIMX8M Nano Digital interfaces.SchDoc: CCIMX8M Nano Digital interfaces
size A3; PageSetup: Record=PageOptions¦CenterHorizontal=True¦CenterVertical=True¦PrintScale=0.70¦XCorrection=1.00¦YCorrection=1.00¦PrintKind=0¦BorderSize=5000000¦LeftOffset=0¦BottomOffset=0¦Orientation=2¦PaperLength=4200¦PaperWidth=2970¦Scale=100¦PaperSource=7¦PrintQuality=600¦MediaType=1¦DitherType=10¦PaperKind=A4¦PrintScaleMode=1; Author: Juan Anzola; SheetNumber: 5; SheetTotal: 21
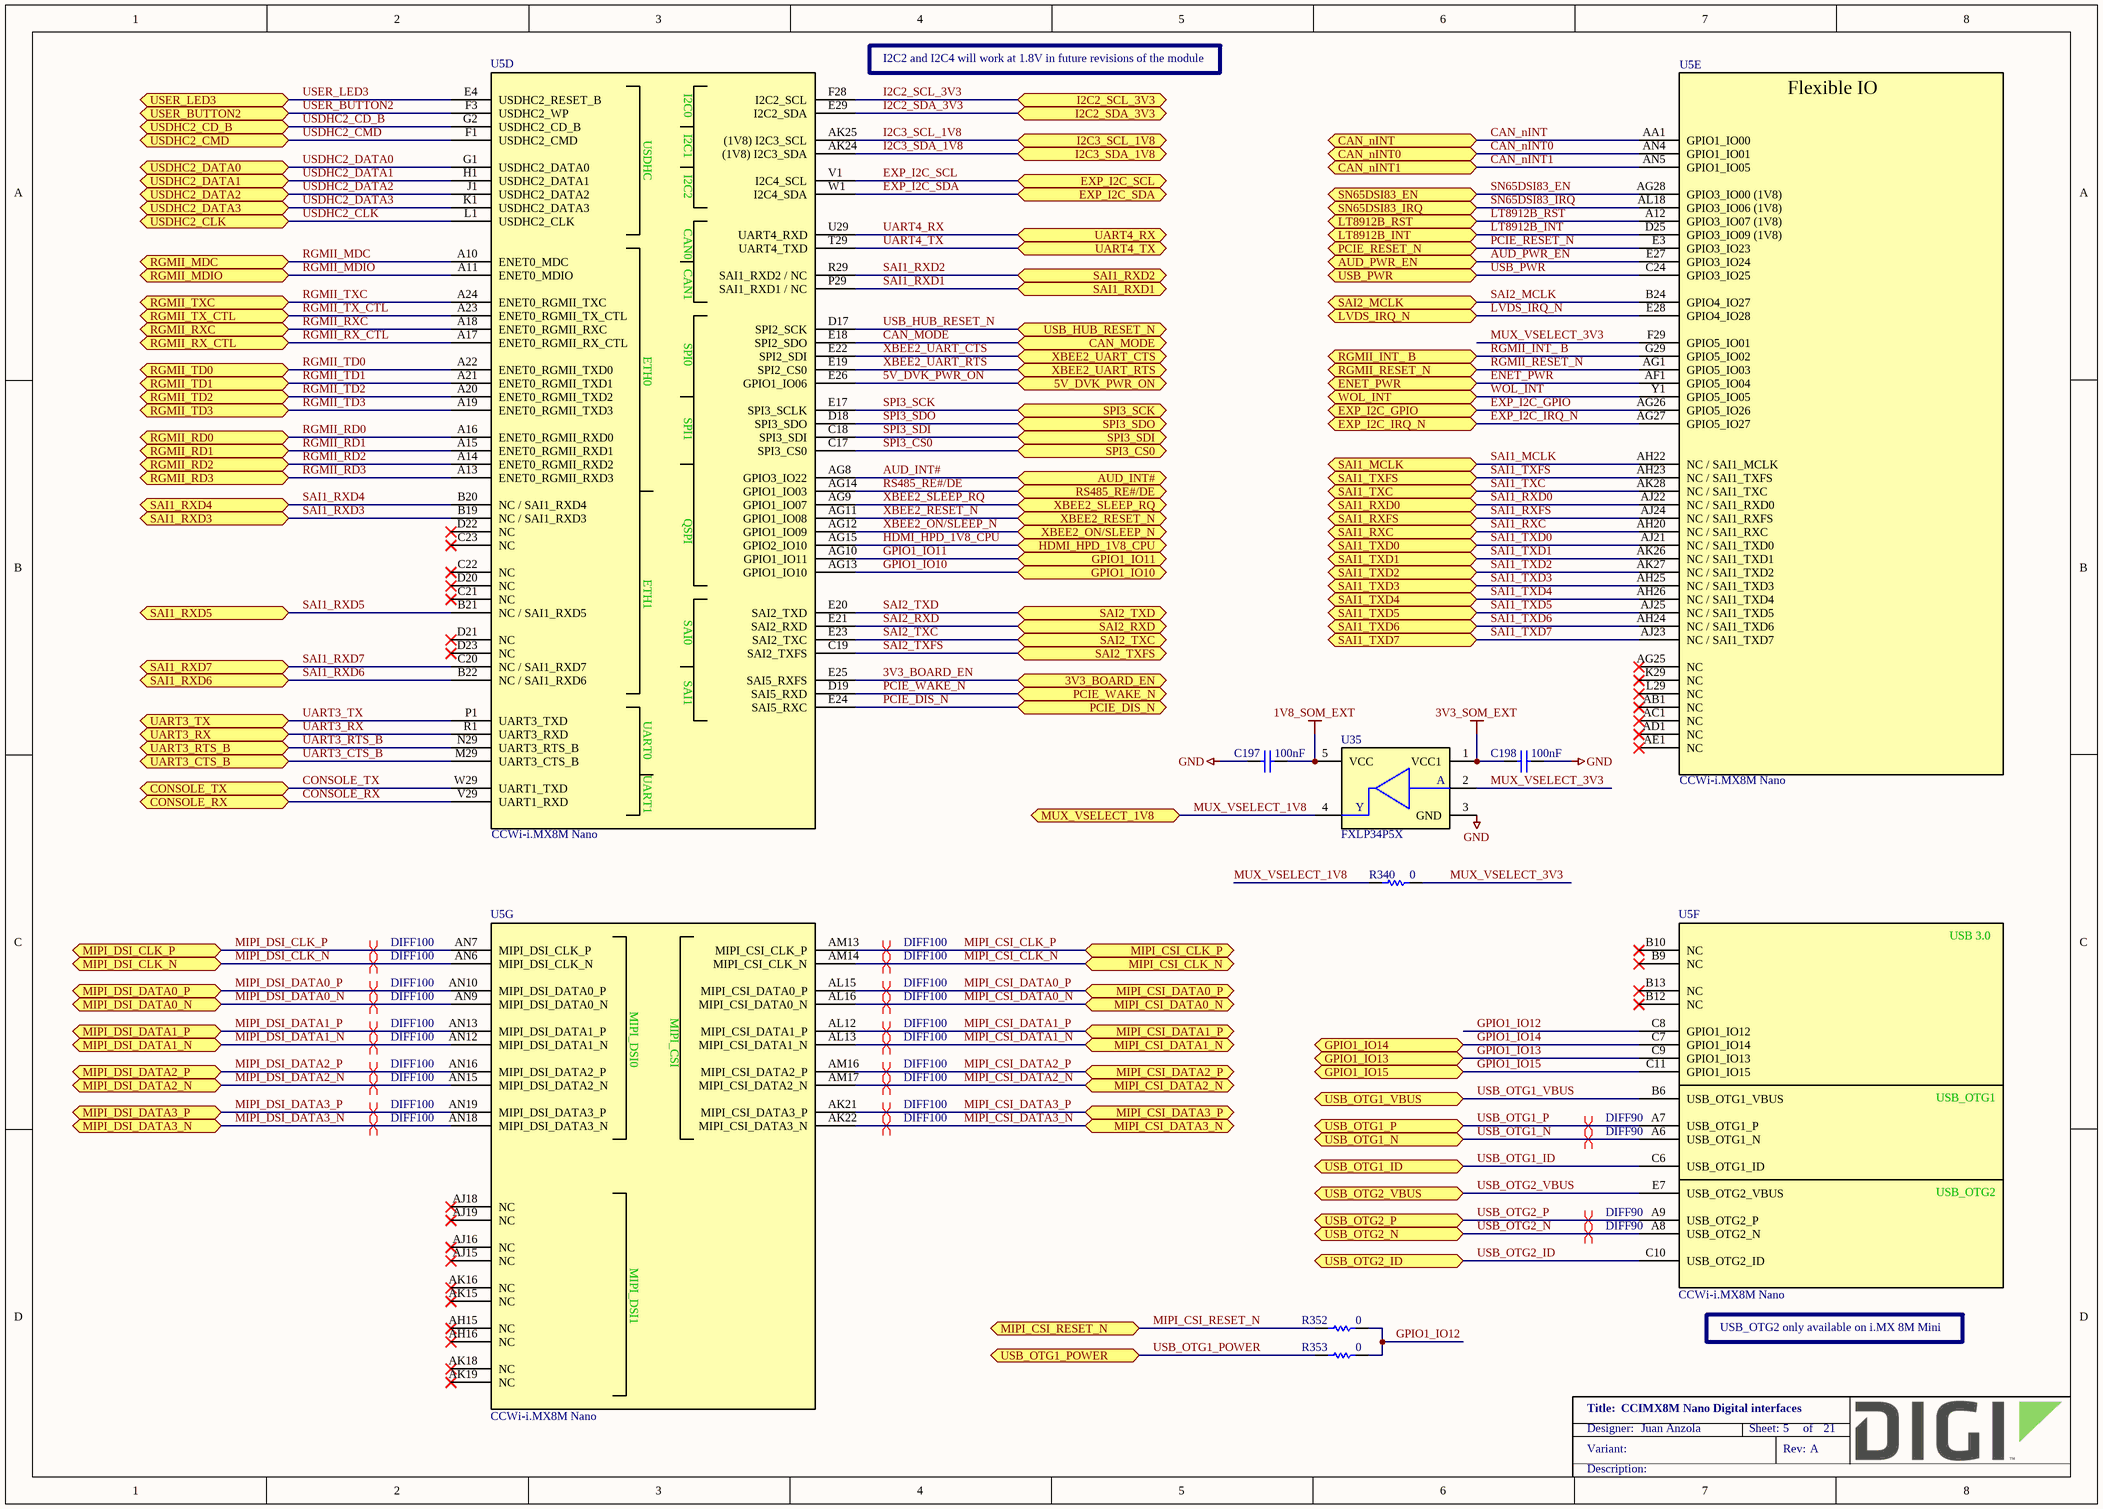
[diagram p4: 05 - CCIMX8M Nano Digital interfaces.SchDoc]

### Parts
C197  100nF  [CAPC1005X55N]
C198  100nF  [CAPC1005X55N]
R340  0  [RESC1005X40N]
R352  0  [RESC1005X40N]
R353  0  [RESC1005X40N]
U5  CCWi-i.MX8M Nano  [E-TEC_LPJ474-129M-32ABEW55L]  (parts D,E,F,G of 10)
U35  FXLP34P5X  [SOT65P210X110-5N]

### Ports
3V3_BOARD_EN (bidir), 5V_DVK_PWR_ON (bidir), AUD_INT# (bidir), AUD_PWR_EN (bidir), CAN_MODE (bidir), CAN_nINT0 (bidir), CAN_nINT1 (bidir), CAN_nINT (bidir), CONSOLE_RX (bidir), CONSOLE_TX (bidir), ENET_PWR (bidir), EXP_I2C_GPIO (bidir), EXP_I2C_IRQ_N (bidir), EXP_I2C_SCL (bidir), EXP_I2C_SDA (bidir), GPIO1_IO10 (bidir), GPIO1_IO11 (bidir), GPIO1_IO13 (bidir), GPIO1_IO14 (bidir), GPIO1_IO15 (bidir), HDMI_HPD_1V8_CPU (bidir), I2C2_SCL_3V3 (bidir), I2C2_SDA_3V3 (bidir), I2C3_SCL_1V8 (bidir), I2C3_SDA_1V8 (bidir), LT8912B_INT (bidir), LT8912B_RST (bidir), LVDS_IRQ_N (bidir), MIPI_CSI_CLK_N (bidir), MIPI_CSI_CLK_P (bidir), MIPI_CSI_DATA0_N (bidir), MIPI_CSI_DATA0_P (bidir), MIPI_CSI_DATA1_N (bidir), MIPI_CSI_DATA1_P (bidir), MIPI_CSI_DATA2_N (bidir), MIPI_CSI_DATA2_P (bidir), MIPI_CSI_DATA3_N (bidir), MIPI_CSI_DATA3_P (bidir), MIPI_CSI_RESET_N (bidir), MIPI_DSI_CLK_N (bidir), MIPI_DSI_CLK_P (bidir), MIPI_DSI_DATA0_N (bidir), MIPI_DSI_DATA0_P (bidir), MIPI_DSI_DATA1_N (bidir), MIPI_DSI_DATA1_P (bidir), MIPI_DSI_DATA2_N (bidir), MIPI_DSI_DATA2_P (bidir), MIPI_DSI_DATA3_N (bidir), MIPI_DSI_DATA3_P (bidir), MUX_VSELECT_1V8 (bidir), PCIE_DIS_N (bidir), PCIE_RESET_N (bidir), PCIE_WAKE_N (bidir), RGMII_INT_ B (bidir), RGMII_MDC (bidir), RGMII_MDIO (bidir), RGMII_RD0 (bidir), RGMII_RD1 (bidir), RGMII_RD2 (bidir), RGMII_RD3 (bidir), RGMII_RESET_N (bidir), RGMII_RX_CTL (bidir), RGMII_RXC (bidir), RGMII_TD0 (bidir), RGMII_TD1 (bidir), RGMII_TD2 (bidir), RGMII_TD3 (bidir), RGMII_TX_CTL (bidir), RGMII_TXC (bidir), RS485_RE#/DE (bidir), SAI1_MCLK (bidir), SAI1_RXC (bidir), SAI1_RXD0 (bidir), SAI1_RXD1 (bidir), SAI1_RXD2 (bidir), SAI1_RXD3 (bidir), SAI1_RXD4 (bidir), SAI1_RXD5 (bidir), SAI1_RXD6 (bidir), SAI1_RXD7 (bidir), SAI1_RXFS (bidir), SAI1_TXC (bidir), SAI1_TXD0 (bidir), SAI1_TXD1 (bidir), SAI1_TXD2 (bidir), SAI1_TXD3 (bidir), SAI1_TXD4 (bidir), SAI1_TXD5 (bidir), SAI1_TXD6 (bidir), SAI1_TXD7 (bidir), SAI1_TXFS (bidir), SAI2_MCLK (bidir), SAI2_RXD (bidir), SAI2_TXC (bidir), SAI2_TXD (bidir), SAI2_TXFS (bidir), SN65DSI83_EN (bidir), SN65DSI83_IRQ (bidir), SPI3_CS0 (bidir), SPI3_SCK (bidir), SPI3_SDI (bidir), SPI3_SDO (bidir), UART3_CTS_B (bidir), UART3_RTS_B (bidir), UART3_RX (bidir), UART3_TX (bidir), UART4_RX (bidir), UART4_TX (bidir), USB_HUB_RESET_N (bidir), USB_OTG1_ID (bidir), USB_OTG1_N (bidir), USB_OTG1_P (bidir), USB_OTG1_POWER (bidir), USB_OTG1_VBUS (bidir), USB_OTG2_ID (bidir), USB_OTG2_N (bidir), USB_OTG2_P (bidir), USB_OTG2_VBUS (bidir), USB_PWR (bidir), USDHC2_CD_B (bidir), USDHC2_CLK (bidir), USDHC2_CMD (bidir), USDHC2_DATA0 (bidir), USDHC2_DATA1 (bidir), USDHC2_DATA2 (bidir), USDHC2_DATA3 (bidir), USER_BUTTON2 (bidir), USER_LED3 (bidir), WOL_INT (bidir), XBEE2_ON/SLEEP_N (bidir), XBEE2_RESET_N (bidir), XBEE2_SLEEP_RQ (bidir), XBEE2_UART_CTS (bidir), XBEE2_UART_RTS (bidir)

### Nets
1V8_SOM_EXT: C197.2 U35.5(VCC)
3V3_SOM_EXT: C198.1 U35.1(VCC1)
GND: C197.1 C198.2 U35.3(GND)
3V3_BOARD_EN: U5.E25(SAI5_RXFS) ; port 3V3_BOARD_EN
5V_DVK_PWR_ON: U5.E26(GPIO1_IO06) ; port 5V_DVK_PWR_ON
AUD_INT#: U5.AG8(GPIO3_IO22) ; port AUD_INT#
AUD_PWR_EN: U5.E27(GPIO3_IO24) ; port AUD_PWR_EN
CAN_MODE: U5.E18(SPI2_SDO) ; port CAN_MODE
CAN_nINT: U5.AA1(GPIO1_IO00) ; port CAN_nINT
CAN_nINT0: U5.AN4(GPIO1_IO01) ; port CAN_nINT0
CAN_nINT1: U5.AN5(GPIO1_IO05) ; port CAN_nINT1
CONSOLE_RX: U5.V29(UART1_RXD) ; port CONSOLE_RX
CONSOLE_TX: U5.W29(UART1_TXD) ; port CONSOLE_TX
ENET_PWR: U5.AF1(GPIO5_IO04) ; port ENET_PWR
EXP_I2C_GPIO: U5.AG26(GPIO5_IO26) ; port EXP_I2C_GPIO
EXP_I2C_IRQ_N: U5.AG27(GPIO5_IO27) ; port EXP_I2C_IRQ_N
EXP_I2C_SCL: U5.V1(I2C4_SCL) ; port EXP_I2C_SCL
EXP_I2C_SDA: U5.W1(I2C4_SDA) ; port EXP_I2C_SDA
GPIO1_IO10: U5.AG13(GPIO1_IO10) ; port GPIO1_IO10
GPIO1_IO11: U5.AG10(GPIO1_IO11) ; port GPIO1_IO11
GPIO1_IO12: R352.2 R353.2 U5.C8(GPIO1_IO12)
GPIO1_IO13: U5.C9(GPIO1_IO13) ; port GPIO1_IO13
GPIO1_IO14: U5.C7(GPIO1_IO14) ; port GPIO1_IO14
GPIO1_IO15: U5.C11(GPIO1_IO15) ; port GPIO1_IO15
HDMI_HPD_1V8_CPU: U5.AG15(GPIO2_IO10) ; port HDMI_HPD_1V8_CPU
I2C2_SCL_3V3: U5.F28(I2C2_SCL) ; port I2C2_SCL_3V3
I2C2_SDA_3V3: U5.E29(I2C2_SDA) ; port I2C2_SDA_3V3
I2C3_SCL_1V8: U5.AK25((1V8)_I2C3_SCL) ; port I2C3_SCL_1V8
I2C3_SDA_1V8: U5.AK24((1V8)_I2C3_SDA) ; port I2C3_SDA_1V8
LT8912B_INT: U5.D25(GPIO3_IO09_(1V8)) ; port LT8912B_INT
LT8912B_RST: U5.A12(GPIO3_IO07_(1V8)) ; port LT8912B_RST
LVDS_IRQ_N: U5.E28(GPIO4_IO28) ; port LVDS_IRQ_N
MIPI_CSI_CLK_N: U5.AM14(MIPI_CSI_CLK_N) ; port MIPI_CSI_CLK_N
MIPI_CSI_CLK_P: U5.AM13(MIPI_CSI_CLK_P) ; port MIPI_CSI_CLK_P
MIPI_CSI_DATA0_N: U5.AL16(MIPI_CSI_DATA0_N) ; port MIPI_CSI_DATA0_N
MIPI_CSI_DATA0_P: U5.AL15(MIPI_CSI_DATA0_P) ; port MIPI_CSI_DATA0_P
MIPI_CSI_DATA1_N: U5.AL13(MIPI_CSI_DATA1_N) ; port MIPI_CSI_DATA1_N
MIPI_CSI_DATA1_P: U5.AL12(MIPI_CSI_DATA1_P) ; port MIPI_CSI_DATA1_P
MIPI_CSI_DATA2_N: U5.AM17(MIPI_CSI_DATA2_N) ; port MIPI_CSI_DATA2_N
MIPI_CSI_DATA2_P: U5.AM16(MIPI_CSI_DATA2_P) ; port MIPI_CSI_DATA2_P
MIPI_CSI_DATA3_N: U5.AK22(MIPI_CSI_DATA3_N) ; port MIPI_CSI_DATA3_N
MIPI_CSI_DATA3_P: U5.AK21(MIPI_CSI_DATA3_P) ; port MIPI_CSI_DATA3_P
MIPI_CSI_RESET_N: R352.1 ; port MIPI_CSI_RESET_N
MIPI_DSI_CLK_N: U5.AN6(MIPI_DSI_CLK_N) ; port MIPI_DSI_CLK_N
MIPI_DSI_CLK_P: U5.AN7(MIPI_DSI_CLK_P) ; port MIPI_DSI_CLK_P
MIPI_DSI_DATA0_N: U5.AN9(MIPI_DSI_DATA0_N) ; port MIPI_DSI_DATA0_N
MIPI_DSI_DATA0_P: U5.AN10(MIPI_DSI_DATA0_P) ; port MIPI_DSI_DATA0_P
MIPI_DSI_DATA1_N: U5.AN12(MIPI_DSI_DATA1_N) ; port MIPI_DSI_DATA1_N
MIPI_DSI_DATA1_P: U5.AN13(MIPI_DSI_DATA1_P) ; port MIPI_DSI_DATA1_P
MIPI_DSI_DATA2_N: U5.AN15(MIPI_DSI_DATA2_N) ; port MIPI_DSI_DATA2_N
MIPI_DSI_DATA2_P: U5.AN16(MIPI_DSI_DATA2_P) ; port MIPI_DSI_DATA2_P
MIPI_DSI_DATA3_N: U5.AN18(MIPI_DSI_DATA3_N) ; port MIPI_DSI_DATA3_N
MIPI_DSI_DATA3_P: U5.AN19(MIPI_DSI_DATA3_P) ; port MIPI_DSI_DATA3_P
MUX_VSELECT_1V8: R340.1 U35.4(Y) ; port MUX_VSELECT_1V8
MUX_VSELECT_3V3: R340.2 U5.F29(GPIO5_IO01) U35.2(A)
PCIE_DIS_N: U5.E24(SAI5_RXC) ; port PCIE_DIS_N
PCIE_RESET_N: U5.E3(GPIO3_IO23) ; port PCIE_RESET_N
PCIE_WAKE_N: U5.D19(SAI5_RXD) ; port PCIE_WAKE_N
RGMII_INT_ B: U5.G29(GPIO5_IO02) ; port RGMII_INT_ B
RGMII_MDC: U5.A10(ENET0_MDC) ; port RGMII_MDC
RGMII_MDIO: U5.A11(ENET0_MDIO) ; port RGMII_MDIO
RGMII_RD0: U5.A16(ENET0_RGMII_RXD0) ; port RGMII_RD0
RGMII_RD1: U5.A15(ENET0_RGMII_RXD1) ; port RGMII_RD1
RGMII_RD2: U5.A14(ENET0_RGMII_RXD2) ; port RGMII_RD2
RGMII_RD3: U5.A13(ENET0_RGMII_RXD3) ; port RGMII_RD3
RGMII_RESET_N: U5.AG1(GPIO5_IO03) ; port RGMII_RESET_N
RGMII_RX_CTL: U5.A17(ENET0_RGMII_RX_CTL) ; port RGMII_RX_CTL
RGMII_RXC: U5.A18(ENET0_RGMII_RXC) ; port RGMII_RXC
RGMII_TD0: U5.A22(ENET0_RGMII_TXD0) ; port RGMII_TD0
RGMII_TD1: U5.A21(ENET0_RGMII_TXD1) ; port RGMII_TD1
RGMII_TD2: U5.A20(ENET0_RGMII_TXD2) ; port RGMII_TD2
RGMII_TD3: U5.A19(ENET0_RGMII_TXD3) ; port RGMII_TD3
RGMII_TX_CTL: U5.A23(ENET0_RGMII_TX_CTL) ; port RGMII_TX_CTL
RGMII_TXC: U5.A24(ENET0_RGMII_TXC) ; port RGMII_TXC
RS485_RE#/DE: U5.AG14(GPIO1_IO03) ; port RS485_RE#/DE
SAI1_MCLK: U5.AH22(NC_/_SAI1_MCLK) ; port SAI1_MCLK
SAI1_RXC: U5.AH20(NC_/_SAI1_RXC) ; port SAI1_RXC
SAI1_RXD0: U5.AJ22(NC_/_SAI1_RXD0) ; port SAI1_RXD0
SAI1_RXD1: U5.P29(SAI1_RXD1_/_NC) ; port SAI1_RXD1
SAI1_RXD2: U5.R29(SAI1_RXD2_/_NC) ; port SAI1_RXD2
SAI1_RXD3: U5.B19(NC_/_SAI1_RXD3) ; port SAI1_RXD3
SAI1_RXD4: U5.B20(NC_/_SAI1_RXD4) ; port SAI1_RXD4
SAI1_RXD5: U5.B21(NC_/_SAI1_RXD5) ; port SAI1_RXD5
SAI1_RXD6: U5.B22(NC_/_SAI1_RXD6) ; port SAI1_RXD6
SAI1_RXD7: U5.C20(NC_/_SAI1_RXD7) ; port SAI1_RXD7
SAI1_RXFS: U5.AJ24(NC_/_SAI1_RXFS) ; port SAI1_RXFS
SAI1_TXC: U5.AK28(NC_/_SAI1_TXC) ; port SAI1_TXC
SAI1_TXD0: U5.AJ21(NC_/_SAI1_TXD0) ; port SAI1_TXD0
SAI1_TXD1: U5.AK26(NC_/_SAI1_TXD1) ; port SAI1_TXD1
SAI1_TXD2: U5.AK27(NC_/_SAI1_TXD2) ; port SAI1_TXD2
SAI1_TXD3: U5.AH25(NC_/_SAI1_TXD3) ; port SAI1_TXD3
SAI1_TXD4: U5.AH26(NC_/_SAI1_TXD4) ; port SAI1_TXD4
SAI1_TXD5: U5.AJ25(NC_/_SAI1_TXD5) ; port SAI1_TXD5
SAI1_TXD6: U5.AH24(NC_/_SAI1_TXD6) ; port SAI1_TXD6
SAI1_TXD7: U5.AJ23(NC_/_SAI1_TXD7) ; port SAI1_TXD7
SAI1_TXFS: U5.AH23(NC_/_SAI1_TXFS) ; port SAI1_TXFS
SAI2_MCLK: U5.B24(GPIO4_IO27) ; port SAI2_MCLK
SAI2_RXD: U5.E21(SAI2_RXD) ; port SAI2_RXD
SAI2_TXC: U5.E23(SAI2_TXC) ; port SAI2_TXC
SAI2_TXD: U5.E20(SAI2_TXD) ; port SAI2_TXD
SAI2_TXFS: U5.C19(SAI2_TXFS) ; port SAI2_TXFS
SN65DSI83_EN: U5.AG28(GPIO3_IO00_(1V8)) ; port SN65DSI83_EN
SN65DSI83_IRQ: U5.AL18(GPIO3_IO06_(1V8)) ; port SN65DSI83_IRQ
SPI3_CS0: U5.C17(SPI3_CS0) ; port SPI3_CS0
SPI3_SCK: U5.E17(SPI3_SCLK) ; port SPI3_SCK
SPI3_SDI: U5.C18(SPI3_SDI) ; port SPI3_SDI
SPI3_SDO: U5.D18(SPI3_SDO) ; port SPI3_SDO
UART3_CTS_B: U5.M29(UART3_CTS_B) ; port UART3_CTS_B
UART3_RTS_B: U5.N29(UART3_RTS_B) ; port UART3_RTS_B
UART3_RX: U5.R1(UART3_RXD) ; port UART3_RX
UART3_TX: U5.P1(UART3_TXD) ; port UART3_TX
UART4_RX: U5.U29(UART4_RXD) ; port UART4_RX
UART4_TX: U5.T29(UART4_TXD) ; port UART4_TX
USB_HUB_RESET_N: U5.D17(SPI2_SCK) ; port USB_HUB_RESET_N
USB_OTG1_ID: U5.C6(USB_OTG1_ID) ; port USB_OTG1_ID
USB_OTG1_N: U5.A6(USB_OTG1_N) ; port USB_OTG1_N
USB_OTG1_P: U5.A7(USB_OTG1_P) ; port USB_OTG1_P
USB_OTG1_POWER: R353.1 ; port USB_OTG1_POWER
USB_OTG1_VBUS: U5.B6(USB_OTG1_VBUS) ; port USB_OTG1_VBUS
USB_OTG2_ID: U5.C10(USB_OTG2_ID) ; port USB_OTG2_ID
USB_OTG2_N: U5.A8(USB_OTG2_N) ; port USB_OTG2_N
USB_OTG2_P: U5.A9(USB_OTG2_P) ; port USB_OTG2_P
USB_OTG2_VBUS: U5.E7(USB_OTG2_VBUS) ; port USB_OTG2_VBUS
USB_PWR: U5.C24(GPIO3_IO25) ; port USB_PWR
USDHC2_CD_B: U5.G2(USDHC2_CD_B) ; port USDHC2_CD_B
USDHC2_CLK: U5.L1(USDHC2_CLK) ; port USDHC2_CLK
USDHC2_CMD: U5.F1(USDHC2_CMD) ; port USDHC2_CMD
USDHC2_DATA0: U5.G1(USDHC2_DATA0) ; port USDHC2_DATA0
USDHC2_DATA1: U5.H1(USDHC2_DATA1) ; port USDHC2_DATA1
USDHC2_DATA2: U5.J1(USDHC2_DATA2) ; port USDHC2_DATA2
USDHC2_DATA3: U5.K1(USDHC2_DATA3) ; port USDHC2_DATA3
USER_BUTTON2: U5.F3(USDHC2_WP) ; port USER_BUTTON2
USER_LED3: U5.E4(USDHC2_RESET_B) ; port USER_LED3
WOL_INT: U5.Y1(GPIO5_IO05) ; port WOL_INT
XBEE2_ON/SLEEP_N: U5.AG12(GPIO1_IO09) ; port XBEE2_ON/SLEEP_N
XBEE2_RESET_N: U5.AG11(GPIO1_IO08) ; port XBEE2_RESET_N
XBEE2_SLEEP_RQ: U5.AG9(GPIO1_IO07) ; port XBEE2_SLEEP_RQ
XBEE2_UART_CTS: U5.E22(SPI2_SDI) ; port XBEE2_UART_CTS
XBEE2_UART_RTS: U5.E19(SPI2_CS0) ; port XBEE2_UART_RTS

Not connected (* = marked no-connect by the designer): U5 AB1(NC)* AC1(NC)* AD1(NC)* AE1(NC)* AG25(NC)* AH15(NC)* AH16(NC)* AJ15(NC)* AJ16(NC)* AJ18(NC)* AJ19(NC)* AK15(NC)* AK16(NC)* AK18(NC)* AK19(NC)* B9(NC)* B10(NC)* B12(NC)* B13(NC)* C21(NC)* C22(NC)* C23(NC)* D20(NC)* D21(NC)* D22(NC)* D23(NC)* K29(NC)* L29(NC)*

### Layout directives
differential pair; net class DIFF100: MIPI_CSI_CLK_N, MIPI_CSI_CLK_P, MIPI_CSI_DATA0_N, MIPI_CSI_DATA0_P, MIPI_CSI_DATA1_N, MIPI_CSI_DATA1_P, MIPI_CSI_DATA2_N, MIPI_CSI_DATA2_P, MIPI_CSI_DATA3_N, MIPI_CSI_DATA3_P, MIPI_DSI_CLK_N, MIPI_DSI_CLK_P, MIPI_DSI_DATA0_N, MIPI_DSI_DATA0_P, MIPI_DSI_DATA1_N, MIPI_DSI_DATA1_P, MIPI_DSI_DATA2_N, MIPI_DSI_DATA2_P, MIPI_DSI_DATA3_N, MIPI_DSI_DATA3_P
differential pair; net class DIFF90: USB_OTG1_N, USB_OTG1_P, USB_OTG2_N, USB_OTG2_P

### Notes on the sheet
- I2C2 and I2C4 will work at 1.8V in future revisions of the module
- USB_OTG2 only available on i.MX 8M Mini

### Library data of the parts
C197 C198 = 1000006: CAP 100nF 16V 10% X7R 0402; Part_Type: Capacitor; Manufacturer: Murata; Manufacturer_Part_Number: GRM155R71C104KA88D; Digi_PN: 14050552; Component_Life_Cycle_State: CAD Reviewed; Area: 0,95; Tolerance: 10
R340 R352 R353 = 1000076: as R16 on sheet 03 - Power, reset
U5 = 1002739: as U5 on sheet 04 - CCIMX8M Nano Power, Control, MCA
U35 = 1000759: TRANSLATOR 1BIT UNIDIRECT SC70-; Part_Type: IC; Manufacturer: Fairchild Semiconductor; Digi_PN: 16051662; Component_Life_Cycle_State: Reviewed; Area: 6,93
